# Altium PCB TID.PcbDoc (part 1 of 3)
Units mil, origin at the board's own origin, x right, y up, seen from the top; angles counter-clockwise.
Board outline 3200 x 2650 mil, 4 copper layers (Top Layer, Mid-Layer 1, Mid-Layer 2, Bottom Layer), stack 61.2 mil thick; 193 components, 108 nets, 523 pads, 202 vias.
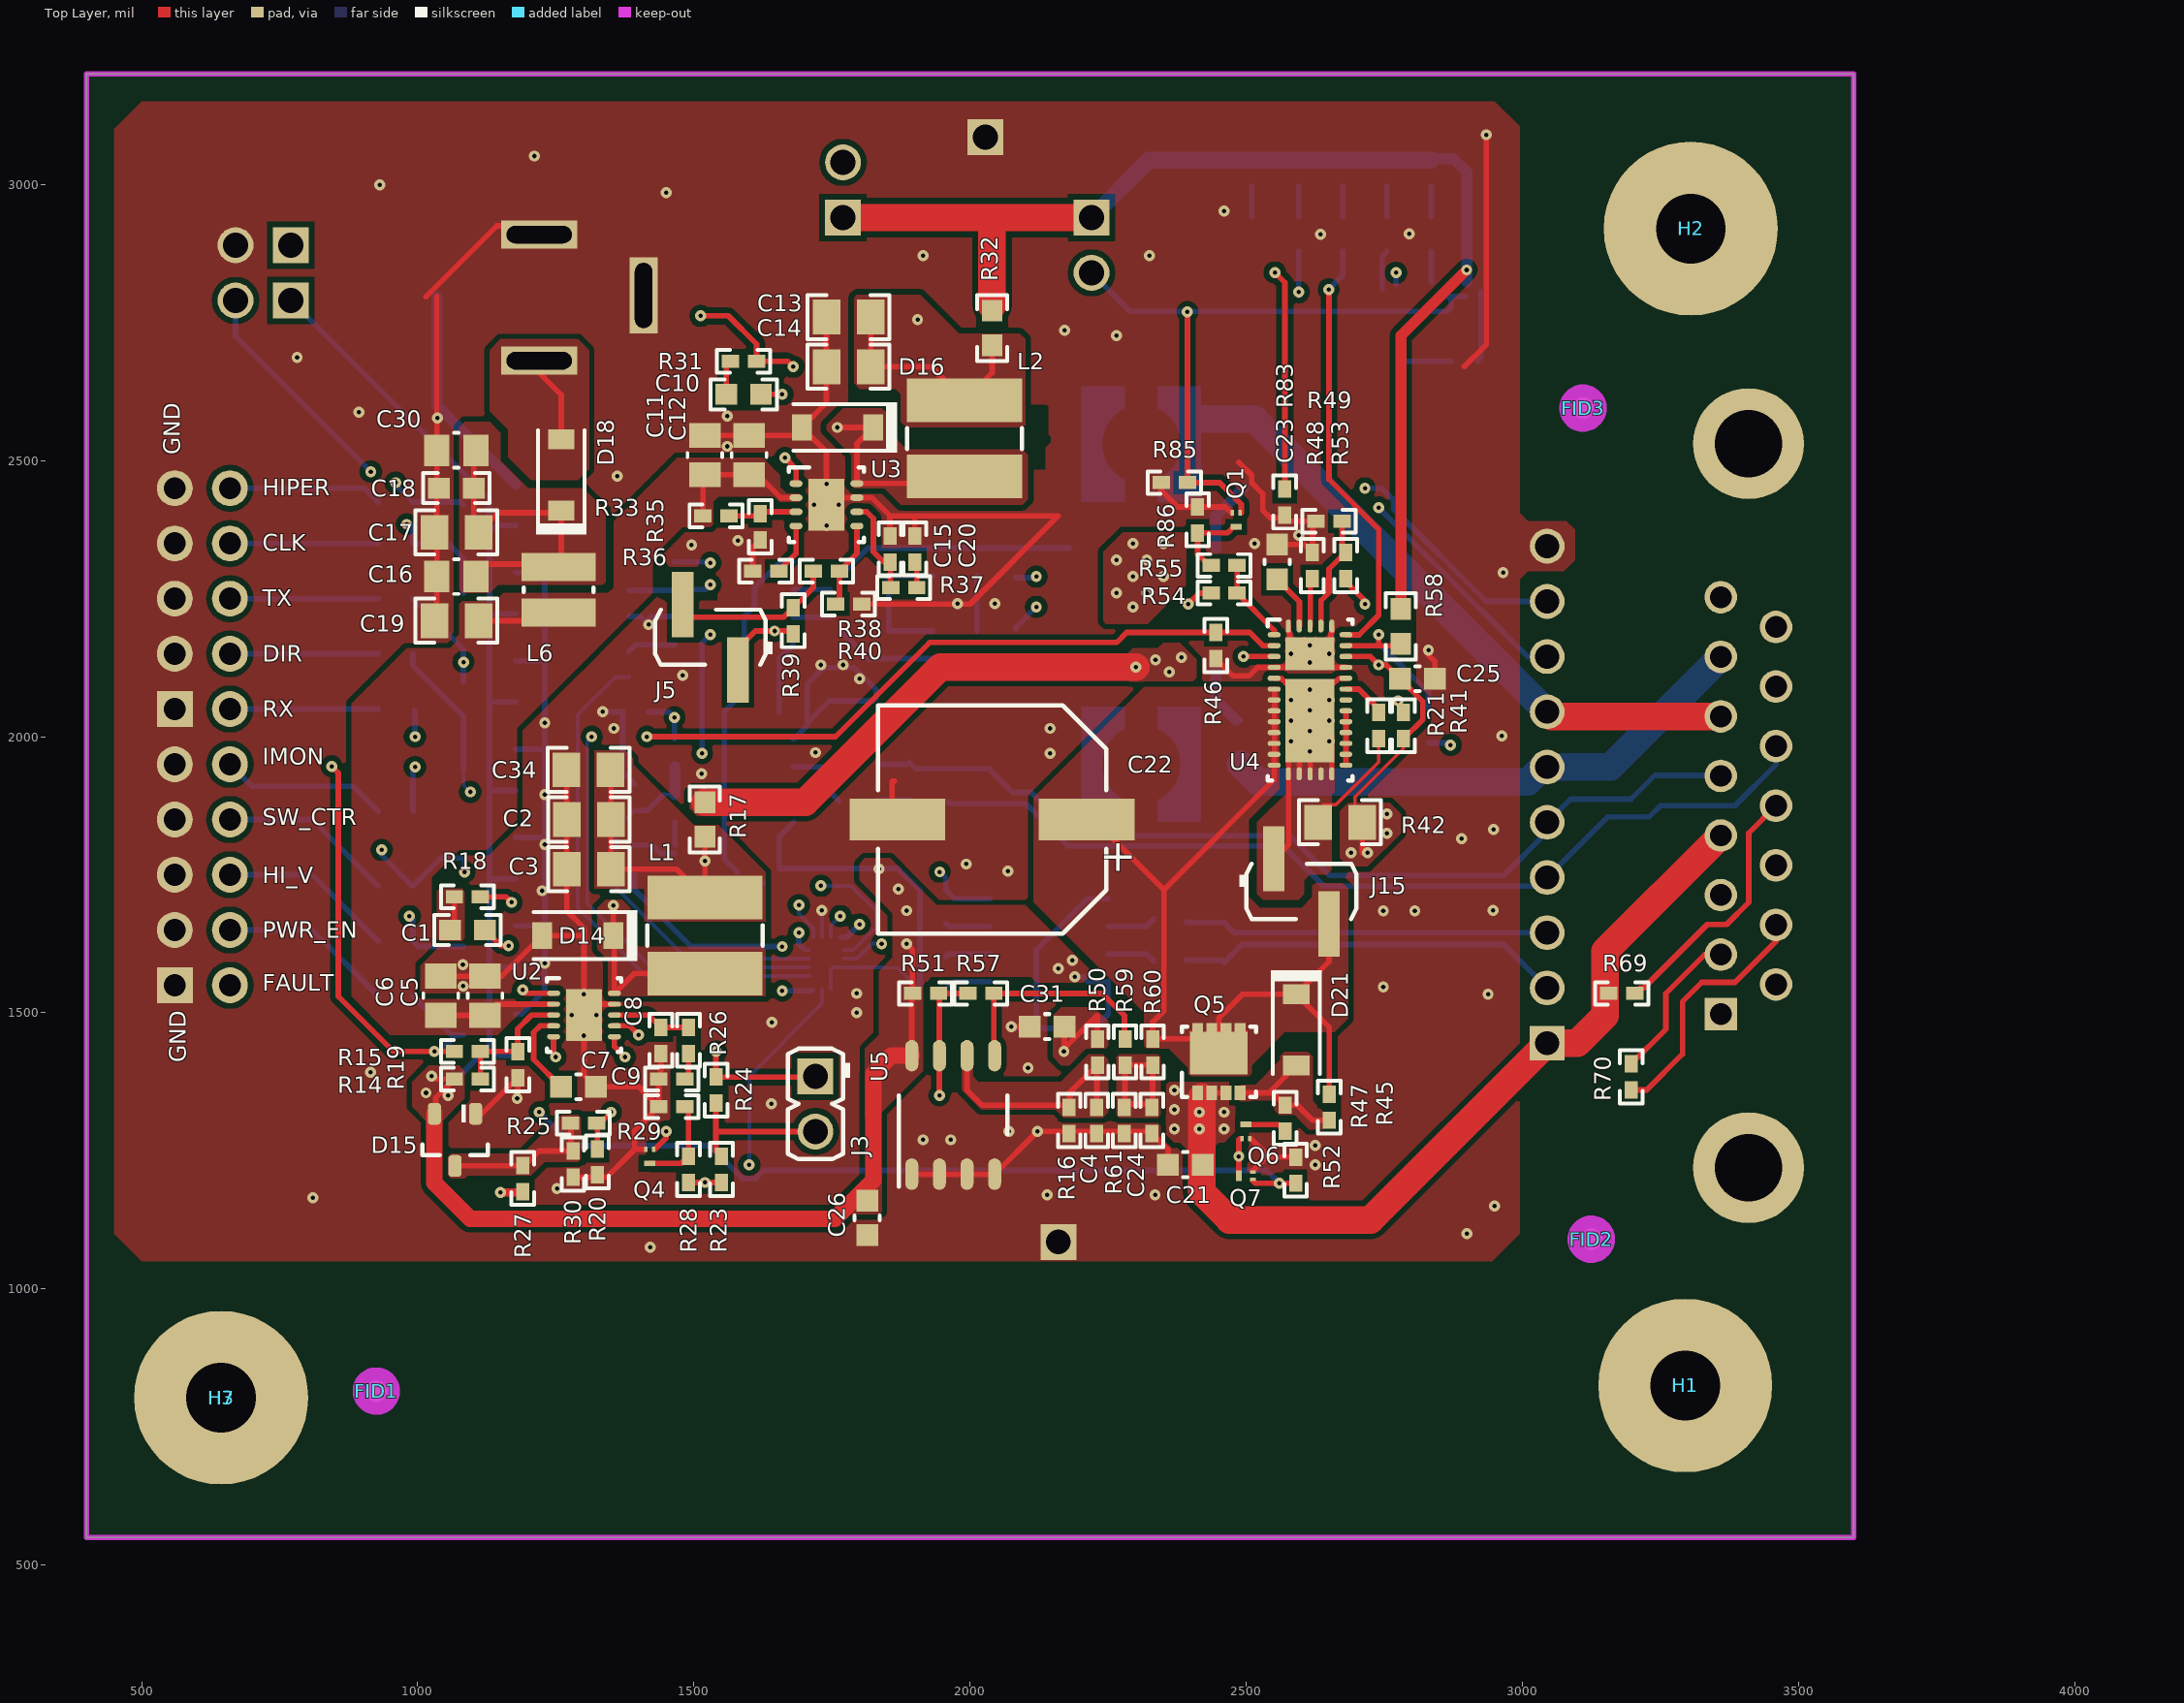
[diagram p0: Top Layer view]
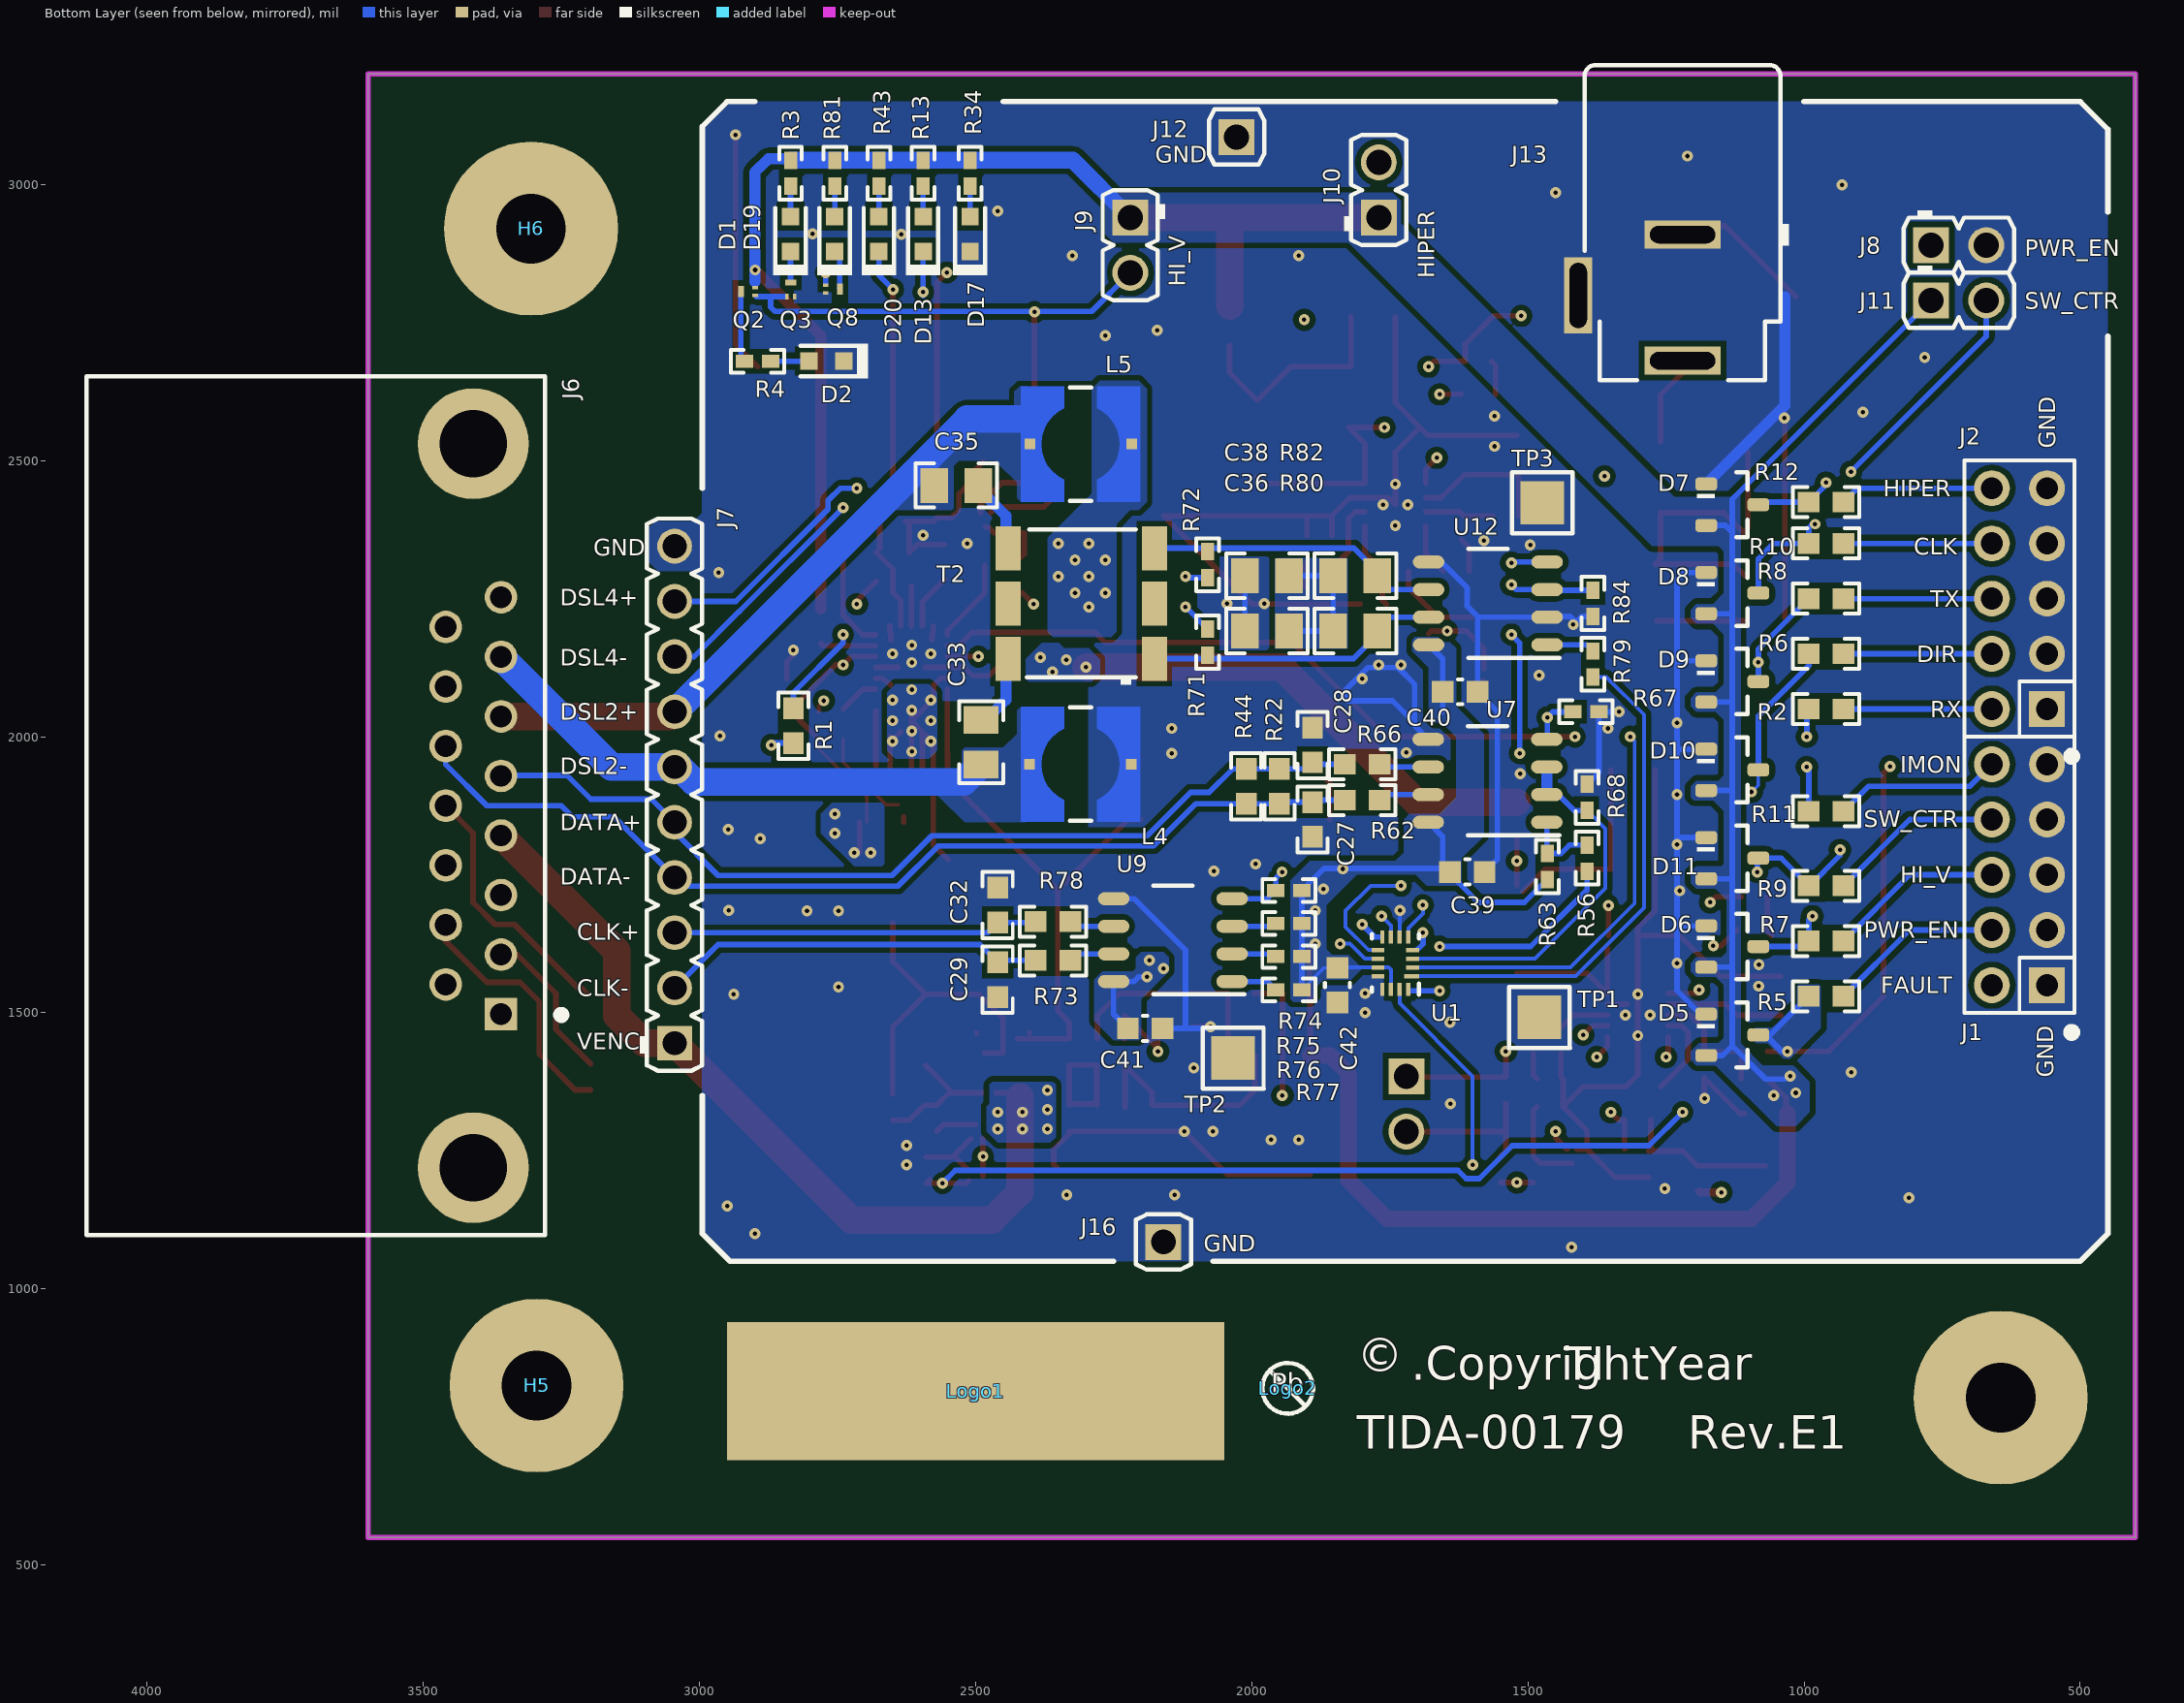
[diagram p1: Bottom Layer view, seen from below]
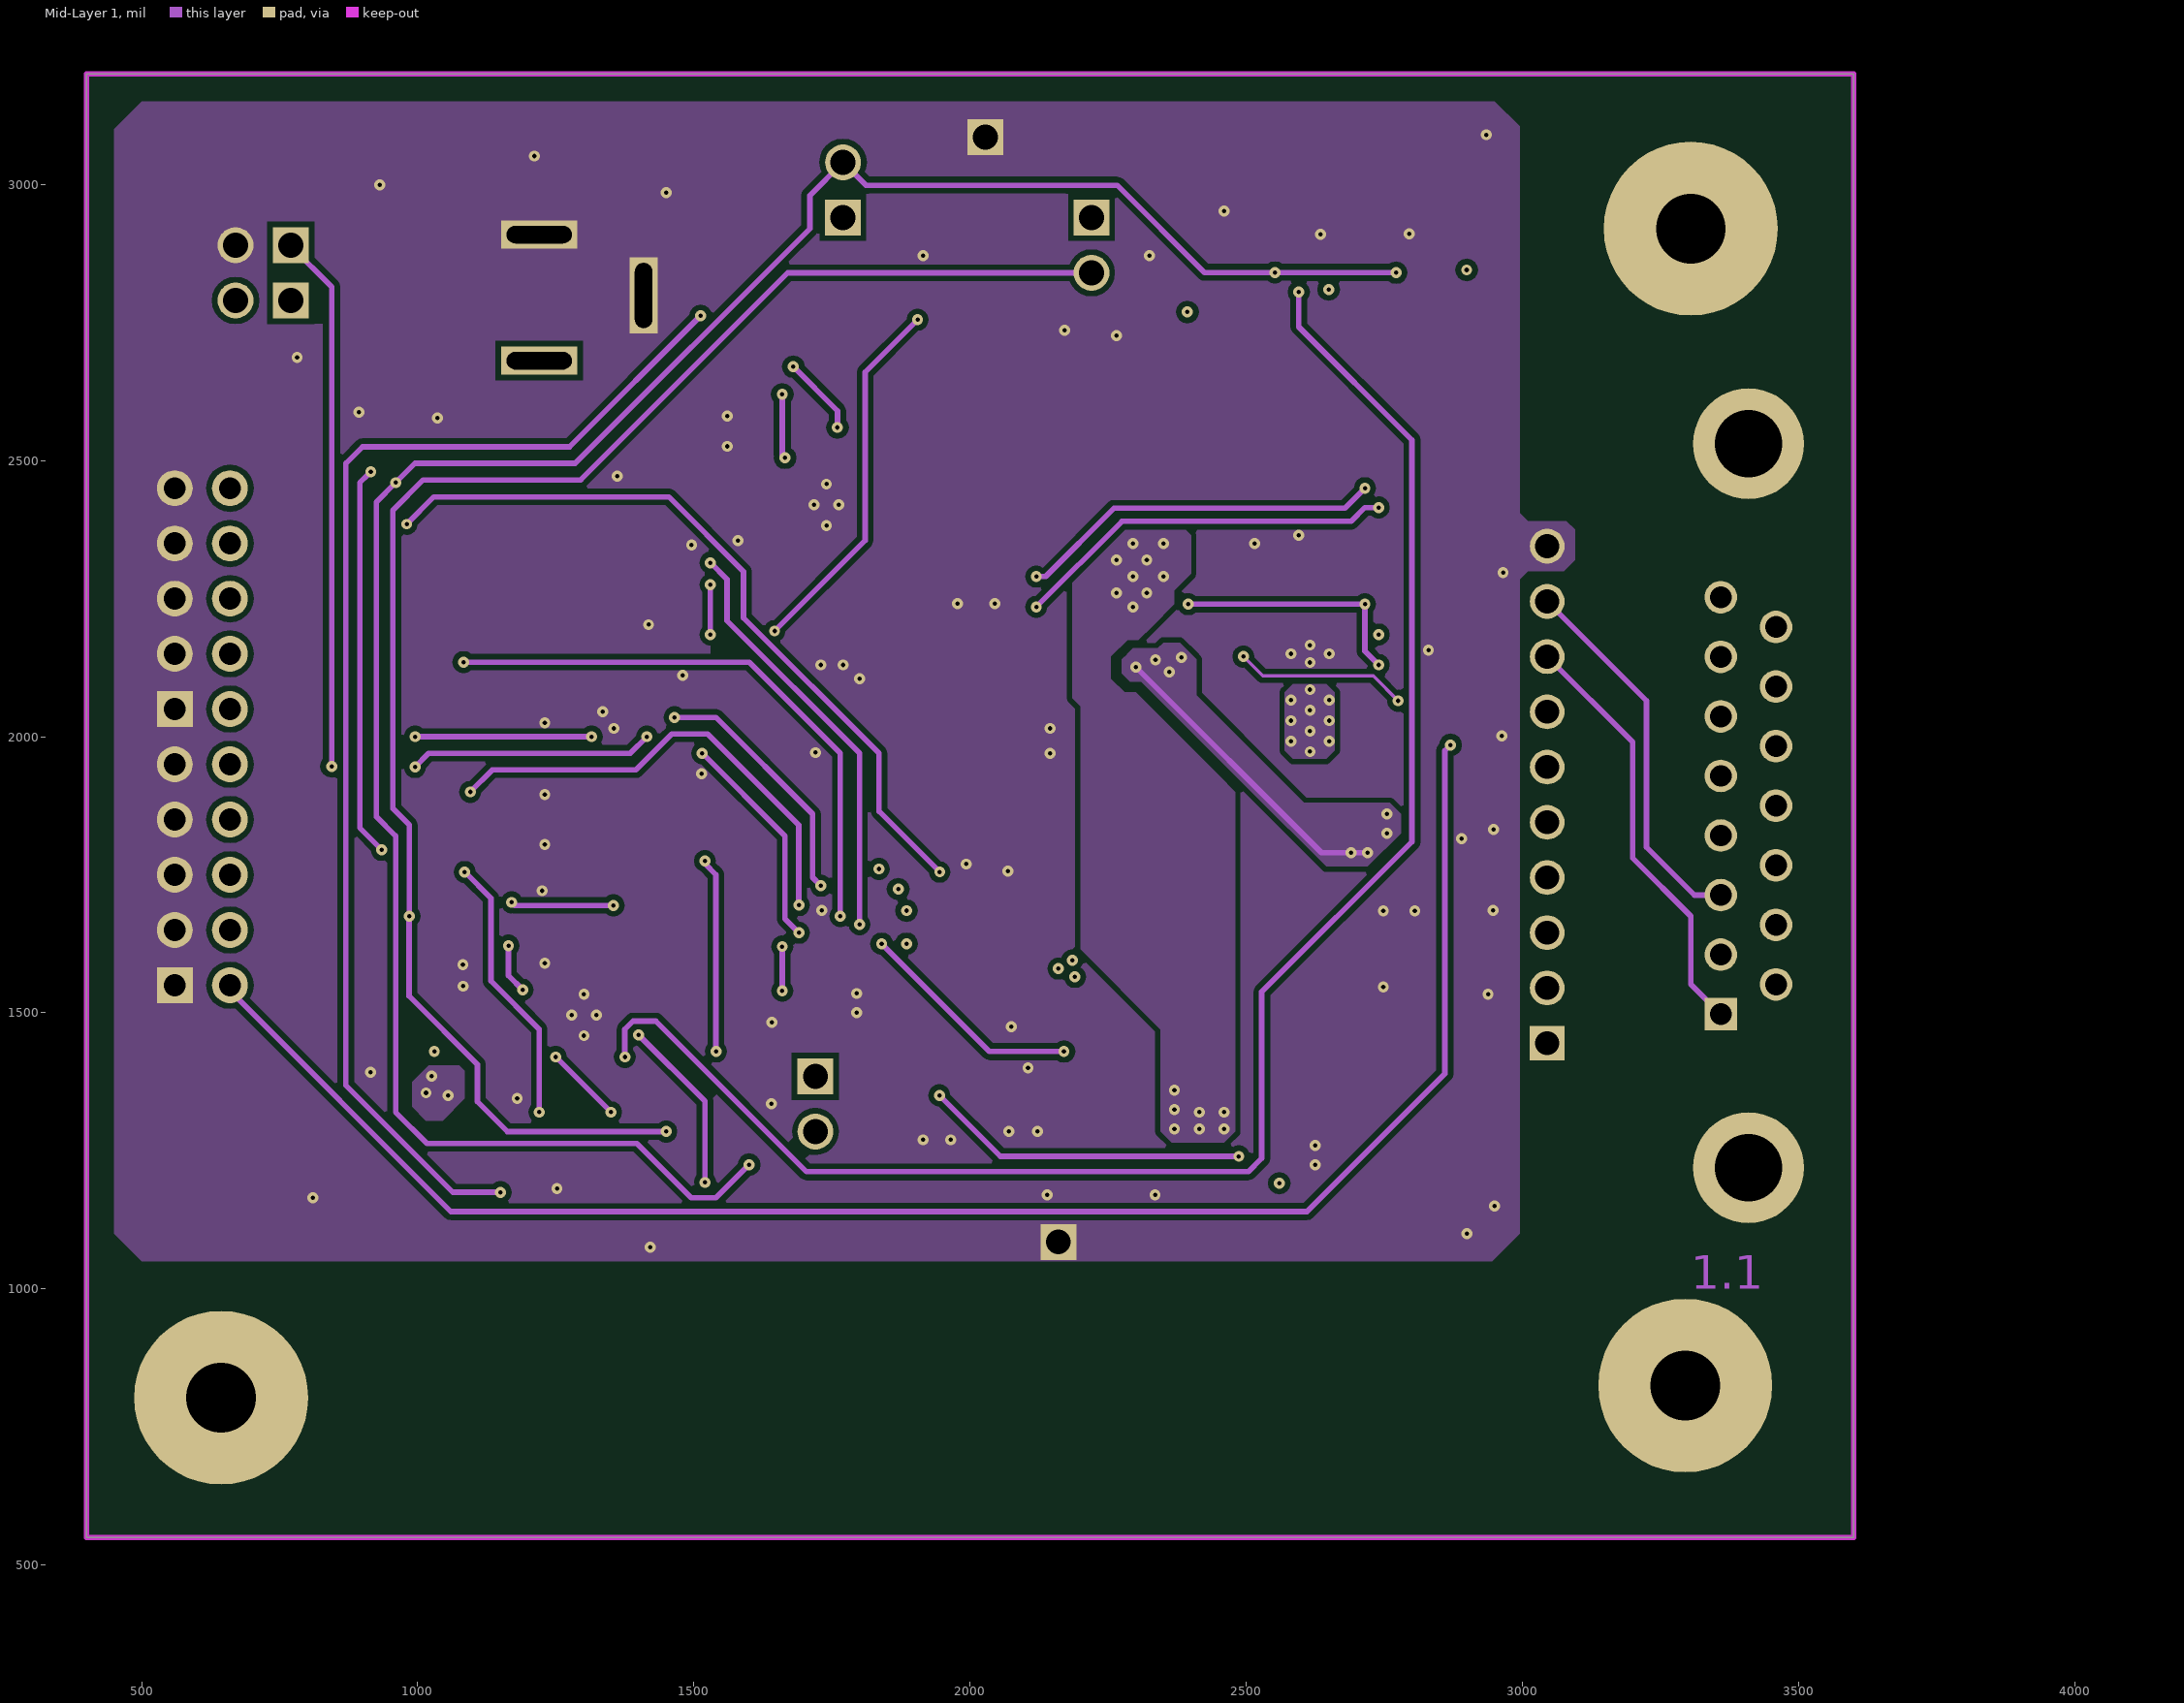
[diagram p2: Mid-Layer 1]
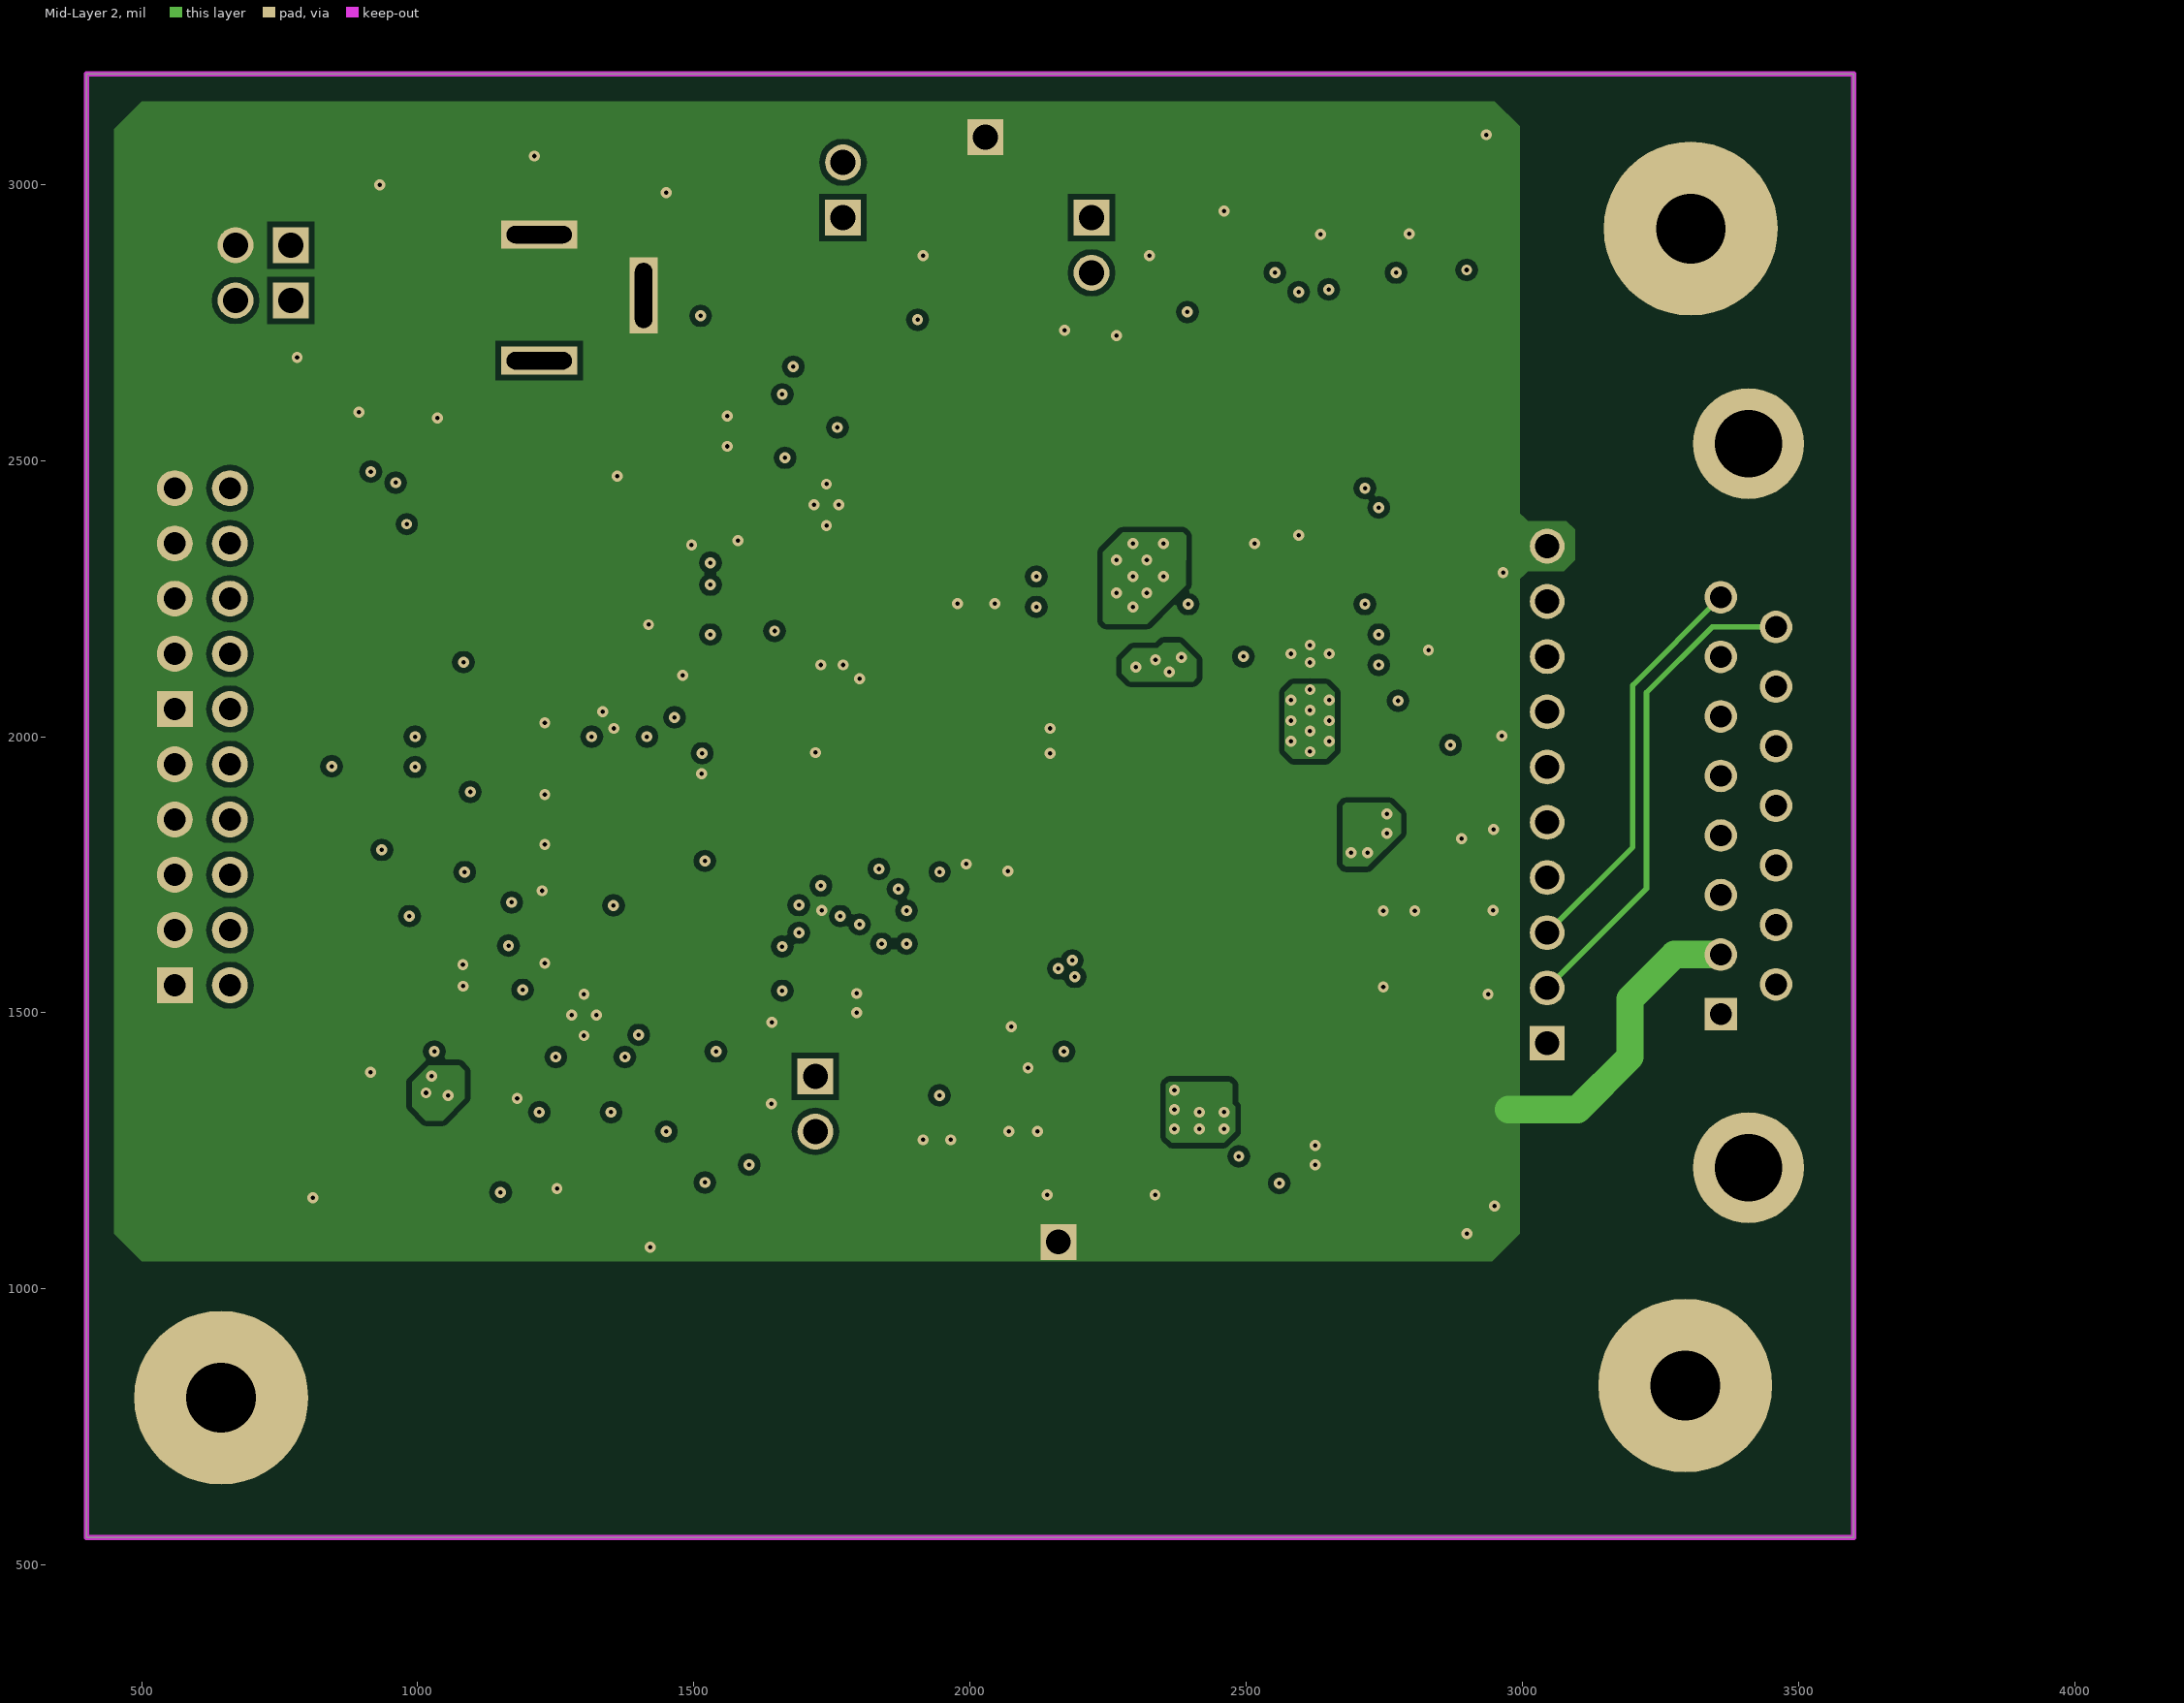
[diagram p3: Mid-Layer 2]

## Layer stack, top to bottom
Top Solder: solder mask 0.4, Solder Resist, Dk 3.5
Top Layer: signal copper 1.4
Dielectric1: core 10, FR-4, Dk 4.2
Mid-Layer 1: signal copper 1.417
Dielectric2: prepreg 35.566, FR-4, Dk 4.2
Mid-Layer 2: signal copper 1.417
Dielectric 3: core 10, FR-4, Dk 4.2
Bottom Layer: signal copper 1.4
Bottom Solder: solder mask 0.4, Solder Resist, Dk 3.5

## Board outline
400,550 3600,550 3600,3200 400,3200

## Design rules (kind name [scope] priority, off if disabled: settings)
AcuteAngle [All] p1: minimum=4.50000000000000E+0001 checktracksonly=FALSE
AssemblyTestPointUsage [All] p1: valid=2
Clearance Clearance_Q5 [(InNet('NetD21_2') AND InComponent('Q5')) vs (InNet('VENCODER') AND InComponent('Q5'))] p1: gap=5.51
Clearance Clearance_FemtoFET [IsPad AND (InComponent('Q1') or InComponent('Q2') or InComponent('Q3') or InComponent('Q4') or InComponent('Q6') or InComponent('Q7') or InComponent('Q8')) vs IsPad AND (InComponent('Q1') or InComponent('Q2') or InComponent('Q3') or InComponent('Q4') or InComponent('Q6') or InComponent('Q7') or InComponent('Q8'))] p2: gap=5.91
Clearance Clearance_Keepouts [((IsTrack Or IsArc) And Not InPoly) And IsFree and IsKeepOut vs ((IsTrack Or IsArc) And Not InPoly) And IsFree and IsKeepOut] p3: gap=0
Clearance Clearance_BoardEdge_MountingHoles [OnCopper and InComponentClass('Mounting Holes') vs IsKeepOut] p4: gap=40
Clearance Clearance_BoardEdge_Poly [OnCopper and InPoly vs IsKeepOut] p5: gap=25
Clearance Clearance_BoardEdge [OnCopper and Not InComponentClass('Logo') and not InComponentClass('FiducialMark') and not InRegion(1000,500,4000,800) and Not IsKeepout vs IsKeepOut] p6: gap=75
Clearance Clearance_Poly [InPolygon] p7: gap=10
Clearance [All] p8: gap=7.87
ComponentClearance ComponentClearance_HEADER [(ObjectKind = 'Component') And ((Name = 'J8') Or (Name='J11') or (Name='J1')or(Name='J2')) vs (ObjectKind = 'Component') And ((Name = 'J8') Or (Name='J11') or (Name='J1')or(Name='J2'))] p1: gap=0 collisioncheckmode=3 verticalgap=0 showdistances=FALSE
ComponentClearance ComponentClearance_MountingHoles_FiducialMarks [InComponentClass('Mounting Holes') vs InComponentClass('FiducialMark')] p2: gap=50 collisioncheckmode=3 verticalgap=10 showdistances=FALSE
ComponentClearance ComponentClearance_Shunt [InComponentClass('Header') vs InComponentClass('Shunt')] p3: gap=0 collisioncheckmode=3 verticalgap=0 showdistances=FALSE
ComponentClearance ComponentClearance_Logo [InComponentClass('Logo')] p4: gap=20 collisioncheckmode=3 verticalgap=10 showdistances=FALSE
ComponentClearance ComponentClearance_ScrewToNut [(HasFootprint('NY PMS 440 0025 PH')) vs (HasFootprint('Keystone_1902C'))] p5: gap=0 collisioncheckmode=3 verticalgap=0 showdistances=FALSE
ComponentClearance ComponentClearance_MountingHoles [InComponentClass('Mounting Holes')] p6: gap=50 collisioncheckmode=3 verticalgap=100000 showdistances=FALSE
ComponentClearance ComponentClearance_SmallPassives [HasFootprint('0201*') or HasFootprint('0402*') or HasFootprint('0508') or HasFootprint('0603*') or HasFootprint('0612') or HasFootprint('0805*') or HasFootprint('0815*') or HasFootprint('0830*') or HasFootprint('1206*') or HasFootprint('1210*') or HasFootprint('1808*') or HasFootprint('1812*') or HasFootprint('1825*') or HasFootprint('2010*') or HasFootprint('2220*') or HasFootprint('2225*') or HasFootprint('2512*') or HasFootprint('2728*') or HasFootprint('3518*') vs HasFootprint('0201*') or HasFootprint('0402*') or HasFootprint('0508') or HasFootprint('0603*') or HasFootprint('0612') or HasFootprint('0805*') or HasFootprint('0815*') or HasFootprint('0830*') or HasFootprint('1206*') or HasFootprint('1210*') or HasFootprint('1808*') or HasFootprint('1812*') or HasFootprint('1825*') or HasFootprint('2010*') or HasFootprint('2220*') or HasFootprint('2225*') or HasFootprint('2512*') or HasFootprint('2728*') or HasFootprint('3518*')] p7: gap=20 collisioncheckmode=3 verticalgap=10 showdistances=FALSE
ComponentClearance ComponentClearance_THtoSMT [IsThruComponent vs IsSMTComponent] p8: gap=80 collisioncheckmode=3 verticalgap=30 showdistances=FALSE
ComponentClearance ComponentClearance_THtoTH [IsThruComponent vs IsThruComponent] p9: gap=80 collisioncheckmode=3 verticalgap=30 showdistances=FALSE
ComponentClearance [All] p10: gap=40 collisioncheckmode=3 verticalgap=10 showdistances=FALSE
DiffPairsRouting [All] p1: maxlimit=100 minlimit=10 mostfreqgap=10 toplayer_minwidth=15 toplayer_maxwidth=15 toplayer_prefwidth=15 midlayer1_minwidth=15 midlayer1_maxwidth=15 midlayer1_prefwidth=15 midlayer2_minwidth=15 midlayer2_maxwidth=15 midlayer2_prefwidth=15 bottomlayer_minwidth=15 bottomlayer_maxwidth=15 bottomlayer_prefwidth=15 maxuncoupledlength=1000
FabricationTestPointUsage TestPointUsage [All] p1: valid=2 allowmultiple=FALSE
FabricationTestpoint Testpoint [All] p1: side=3 testpointundercomponent=TRUE minsize=40 maxsize=100 preferedsize=60 minholesize=0 maxholesize=40 preferedholesize=32 testpointgrid=1 allowsidetop=TRUE allowsidebottom=TRUE usegrid=TRUE gridtolerance=0.01
FanoutControl Fanout_LCC [IsLCC] p1: bgadir=Out bgaviamode=Centered fanoutstyle=Auto fanoutdirection=Alternating viagrid=1 // Fanout_LCC (Default Rule)
FanoutControl Fanout_BGA [IsBGA] p2: bgadir=Out bgaviamode=Centered fanoutstyle=Auto fanoutdirection=Alternating viagrid=1 // Fanout_BGA (Default Rule)
FanoutControl Fanout_Default [All] p4: bgadir=Out bgaviamode=Centered fanoutstyle=Auto fanoutdirection=Alternating viagrid=1 // Fanout_Default (Default Rule)
FanoutControl Fanout_Small [(CompPinCount < 5)] p5: bgadir=Out bgaviamode=Centered fanoutstyle=Auto fanoutdirection=OutThenIn viagrid=1 // Fanout_Small (Default Rule)
HoleSize [All] p1: absolutevalues=TRUE maxlimit=251 minlimit=7 maxpercent=80.000 minpercent=20.000
MinimumAnnularRing MinimumAnnularRing_ThermalPadVias [IsVia and InAnyComponent] p1: minimumring=5
MinimumAnnularRing [All] p2: minimumring=5
MinimumSolderMaskSliver MinimumSolderMaskSliver_Logo [InComponentClass('Logo') vs InComponentClass('Logo')] p1: minsoldermaskwidth=0.7
MinimumSolderMaskSliver [All] p2: minsoldermaskwidth=2
NetAntennae [not(InComponent ('U4') and IsVia)] p1: netantennaetolerance=0
PlaneConnect [All] p1: planeconnectstyle=Relief reliefexpansion=10 reliefentries=4 reliefconductorwidth=10 reliefairgap=10
PolygonConnect PolygonConnect_47 [All vs IsNamedPolygon('Top Layer -GND')] p1: connectstyle=Direct reliefconductorwidth=10 reliefentries=4 polygonreliefangle="90 Angle" airgapwidth=10
PolygonConnect PolygonConnect_46 [All vs IsNamedPolygon('Top Layer-No Net 9')] p2: connectstyle=Direct reliefconductorwidth=10 reliefentries=4 polygonreliefangle="90 Angle" airgapwidth=10
PolygonConnect PolygonConnect_45 [All vs IsNamedPolygon('Top Layer-No Net 9')] p3: connectstyle=Direct reliefconductorwidth=10 reliefentries=4 polygonreliefangle="90 Angle" airgapwidth=10
PolygonConnect PolygonConnect_44 [All vs IsNamedPolygon('Top Layer-No Net 9')] p4: connectstyle=Direct reliefconductorwidth=10 reliefentries=4 polygonreliefangle="90 Angle" airgapwidth=10
PolygonConnect PolygonConnect_43 [All vs IsNamedPolygon('Top Layer-No Net 9')] p5: connectstyle=Direct reliefconductorwidth=10 reliefentries=4 polygonreliefangle="90 Angle" airgapwidth=10
PolygonConnect PolygonConnect_42 [All vs IsNamedPolygon('Top Layer-No Net 9')] p6: connectstyle=Direct reliefconductorwidth=10 reliefentries=4 polygonreliefangle="90 Angle" airgapwidth=10
PolygonConnect PolygonConnect_41 [All vs IsNamedPolygon('Top Layer-No Net 9')] p7: connectstyle=Direct reliefconductorwidth=10 reliefentries=4 polygonreliefangle="90 Angle" airgapwidth=10
PolygonConnect PolygonConnect_40 [All vs IsNamedPolygon('Top Layer-No Net 8')] p8: connectstyle=Direct reliefconductorwidth=10 reliefentries=4 polygonreliefangle="90 Angle" airgapwidth=10
PolygonConnect PolygonConnect_39 [All vs IsNamedPolygon('Top Layer-No Net 8')] p9: connectstyle=Direct reliefconductorwidth=10 reliefentries=4 polygonreliefangle="90 Angle" airgapwidth=10
PolygonConnect PolygonConnect_38 [All vs IsNamedPolygon('Top Layer-No Net 7')] p10: connectstyle=Direct reliefconductorwidth=10 reliefentries=4 polygonreliefangle="90 Angle" airgapwidth=10
PolygonConnect PolygonConnect_37 [All vs IsNamedPolygon('Top Layer-No Net 7')] p11: connectstyle=Direct reliefconductorwidth=10 reliefentries=4 polygonreliefangle="90 Angle" airgapwidth=10
PolygonConnect PolygonConnect_36 [All vs IsNamedPolygon('Bottom Layer-No Net 3')] p12: connectstyle=Direct reliefconductorwidth=10 reliefentries=4 polygonreliefangle="90 Angle" airgapwidth=10
PolygonConnect PolygonConnect_35 [All vs IsNamedPolygon('Bottom Layer-No Net 3')] p13: connectstyle=Direct reliefconductorwidth=10 reliefentries=4 polygonreliefangle="90 Angle" airgapwidth=10
PolygonConnect PolygonConnect_34 [All vs IsNamedPolygon('Bottom Layer-No Net 3')] p14: connectstyle=Direct reliefconductorwidth=10 reliefentries=4 polygonreliefangle="90 Angle" airgapwidth=10
PolygonConnect PolygonConnect_33 [All vs IsNamedPolygon('Bottom Layer-No Net 2')] p15: connectstyle=Direct reliefconductorwidth=10 reliefentries=4 polygonreliefangle="90 Angle" airgapwidth=10
PolygonConnect PolygonConnect_32 [All vs IsNamedPolygon('Bottom Layer-No Net')] p16: connectstyle=Direct reliefconductorwidth=10 reliefentries=4 polygonreliefangle="90 Angle" airgapwidth=10
PolygonConnect PolygonConnect_31 [All vs IsNamedPolygon('Bottom Layer-No Net 1')] p17: connectstyle=Direct reliefconductorwidth=10 reliefentries=4 polygonreliefangle="90 Angle" airgapwidth=10
PolygonConnect PolygonConnect_30 [All vs IsNamedPolygon('Bottom Layer-No Net')] p18: connectstyle=Direct reliefconductorwidth=10 reliefentries=4 polygonreliefangle="90 Angle" airgapwidth=10
PolygonConnect PolygonConnect_29 [All vs IsNamedPolygon('Bottom Layer-No Net 1')] p19: connectstyle=Direct reliefconductorwidth=10 reliefentries=4 polygonreliefangle="90 Angle" airgapwidth=10
PolygonConnect PolygonConnect_28 [All vs IsNamedPolygon('Top Layer -GND')] p20: connectstyle=Direct reliefconductorwidth=10 reliefentries=4 polygonreliefangle="90 Angle" airgapwidth=10
PolygonConnect PolygonConnect_27 [All vs IsNamedPolygon('Top Layer -GND')] p21: connectstyle=Direct reliefconductorwidth=10 reliefentries=4 polygonreliefangle="90 Angle" airgapwidth=10
PolygonConnect PolygonConnect_26 [All vs IsNamedPolygon('Top Layer -GND')] p22: connectstyle=Direct reliefconductorwidth=10 reliefentries=4 polygonreliefangle="90 Angle" airgapwidth=10
PolygonConnect PolygonConnect_25 [All vs IsNamedPolygon('Top Layer -VIN')] p23: connectstyle=Direct reliefconductorwidth=10 reliefentries=4 polygonreliefangle="90 Angle" airgapwidth=10
PolygonConnect PolygonConnect_24 [All vs IsNamedPolygon('Top Layer -VIN')] p24: connectstyle=Direct reliefconductorwidth=10 reliefentries=4 polygonreliefangle="90 Angle" airgapwidth=10
PolygonConnect PolygonConnect_23 [All vs IsNamedPolygon('Top Layer -VIN')] p25: connectstyle=Direct reliefconductorwidth=10 reliefentries=4 polygonreliefangle="90 Angle" airgapwidth=10
PolygonConnect PolygonConnect_22 [All vs IsNamedPolygon('Top Layer-No Net 4')] p26: connectstyle=Direct reliefconductorwidth=10 reliefentries=4 polygonreliefangle="90 Angle" airgapwidth=10
PolygonConnect PolygonConnect_21 [All vs IsNamedPolygon('Top Layer-No Net 6')] p27: connectstyle=Direct reliefconductorwidth=10 reliefentries=4 polygonreliefangle="90 Angle" airgapwidth=10
PolygonConnect PolygonConnect_20 [All vs IsNamedPolygon('Top Layer-No Net')] p28: connectstyle=Direct reliefconductorwidth=10 reliefentries=4 polygonreliefangle="90 Angle" airgapwidth=10
PolygonConnect PolygonConnect_19 [All vs IsNamedPolygon('Top Layer-No Net 1')] p29: connectstyle=Direct reliefconductorwidth=10 reliefentries=4 polygonreliefangle="90 Angle" airgapwidth=10
PolygonConnect PolygonConnect_18 [All vs IsNamedPolygon('Top Layer -PHASE')] p30: connectstyle=Direct reliefconductorwidth=10 reliefentries=4 polygonreliefangle="90 Angle" airgapwidth=10
PolygonConnect PolygonConnect_17 [All vs IsNamedPolygon('Bottom Layer -GND')] p31: connectstyle=Direct reliefconductorwidth=10 reliefentries=4 polygonreliefangle="90 Angle" airgapwidth=10
PolygonConnect PolygonConnect_16 [All vs IsNamedPolygon('Top Layer-No Net 3')] p32: connectstyle=Direct reliefconductorwidth=10 reliefentries=4 polygonreliefangle="90 Angle" airgapwidth=10
PolygonConnect PolygonConnect_15 [All vs IsNamedPolygon('Mid-Layer 2 -GND')] p33: connectstyle=Direct reliefconductorwidth=10 reliefentries=4 polygonreliefangle="90 Angle" airgapwidth=10
PolygonConnect PolygonConnect_14 [All vs IsNamedPolygon('Top Layer -VENCODER')] p34: connectstyle=Direct reliefconductorwidth=10 reliefentries=4 polygonreliefangle="90 Angle" airgapwidth=10
PolygonConnect PolygonConnect_13 [All vs IsNamedPolygon('Top Layer-No Net 2')] p35: connectstyle=Direct reliefconductorwidth=10 reliefentries=4 polygonreliefangle="90 Angle" airgapwidth=10
PolygonConnect PolygonConnect_12 [All vs IsNamedPolygon('Top Layer-No Net 5')] p36: connectstyle=Direct reliefconductorwidth=10 reliefentries=4 polygonreliefangle="90 Angle" airgapwidth=10
PolygonConnect PolygonConnect_11 [All vs IsNamedPolygon('Top Layer -VOUT_EFUSE')] p37: connectstyle=Direct reliefconductorwidth=10 reliefentries=4 polygonreliefangle="90 Angle" airgapwidth=10
PolygonConnect PolygonConnect_10 [All vs IsNamedPolygon('Top Layer-No Net 3')] p38: connectstyle=Direct reliefconductorwidth=10 reliefentries=4 polygonreliefangle="90 Angle" airgapwidth=10
PolygonConnect PolygonConnect_9 [All vs IsNamedPolygon('Top Layer-No Net')] p39: connectstyle=Direct reliefconductorwidth=10 reliefentries=4 polygonreliefangle="90 Angle" airgapwidth=10
PolygonConnect PolygonConnect_8 [All vs IsNamedPolygon('Mid-Layer 2 -GND')] p40: connectstyle=Direct reliefconductorwidth=10 reliefentries=4 polygonreliefangle="90 Angle" airgapwidth=10
PolygonConnect PolygonConnect_7 [All vs IsNamedPolygon('Top Layer -VENCODER')] p41: connectstyle=Direct reliefconductorwidth=10 reliefentries=4 polygonreliefangle="90 Angle" airgapwidth=10
PolygonConnect PolygonConnect_6 [All vs IsNamedPolygon('Top Layer -PHASE')] p42: connectstyle=Direct reliefconductorwidth=10 reliefentries=4 polygonreliefangle="90 Angle" airgapwidth=10
PolygonConnect PolygonConnect_5 [All vs IsNamedPolygon('Top Layer -VOUT_EFUSE')] p43: connectstyle=Direct reliefconductorwidth=10 reliefentries=4 polygonreliefangle="90 Angle" airgapwidth=10
PolygonConnect PolygonConnect_4 [All vs IsNamedPolygon('Bottom Layer -GND')] p44: connectstyle=Direct reliefconductorwidth=10 reliefentries=4 polygonreliefangle="90 Angle" airgapwidth=10
PolygonConnect PolygonConnect_3 [All vs IsNamedPolygon('Mid-Layer 2-No Net')] p45: connectstyle=Direct reliefconductorwidth=10 reliefentries=4 polygonreliefangle="90 Angle" airgapwidth=10
PolygonConnect PolygonConnect_2 [All vs IsNamedPolygon('GND')] p46: connectstyle=Direct reliefconductorwidth=10 reliefentries=4 polygonreliefangle="90 Angle" airgapwidth=10
PolygonConnect PolygonConnect_1 [All vs IsNamedPolygon('Bottom Layer-No Net')] p47: connectstyle=Direct reliefconductorwidth=10 reliefentries=4 polygonreliefangle="90 Angle" airgapwidth=10
PolygonConnect [All] p48: connectstyle=Relief reliefconductorwidth=10 reliefentries=4 polygonreliefangle="90 Angle" airgapwidth=10
RoutingVias ThermalPadVias [IsVia and InAnyComponent] p1: holewidth=7.87 width=19.68 viastyle="Through Hole" minholewidth=7 minwidth=19.68 maxholewidth=13 maxwidth=23.62
RoutingVias [All] p2: holewidth=16 width=34 viastyle="Through Hole" minholewidth=7.87 minwidth=19 maxholewidth=40 maxwidth=65
SilkToBoardRegionClearance [Not ((IsComment or IsDesignator) And (Hide <> 'False')) and not (InRegion(1000,500,4000,800) or InRegion(1600,4700,2200,4785) or InRegion(4700,2500,4850,4250))] p1:
SilkToSilkClearance SilkToSilkClearance_Pb-FreeLogo [(HasFootprint('Pb-Free_Overlay_Medium') OR HasFootprint('Pb-Free_Overlay_Small')) vs (HasFootprint('Pb-Free_Overlay_Medium') OR HasFootprint('Pb-Free_Overlay_Small'))] p1: silktosilkclearance=0
SilkToSilkClearance [All] p2: silktosilkclearance=0
SilkToSolderMaskClearance "Silk to Solder Mask Opening" [not (IsVia) vs not (IsVia)] p1: minsilkscreentomaskgap=0 clearancetoexposedcopper=FALSE
SolderMaskExpansion [All] p1: expansion=1.97
UnpouredPolygon [All] p1: allowunpoured=FALSE
Width [All] p1: maxlimit=100 minlimit=6 preferedwidth=10 checkconnectedcopper=TRUE
13 further rules are at their usual default settings.

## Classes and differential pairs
component class "Mounting Holes": H1 H2 H3
component class Logo: Logo1
component class TID_Hardware: FID1 FID2 FID3 H1 H2 H3 H5 H6 H7 Logo1 Logo2
component class FiducialMark: FID1 FID2 FID3
component class Header: J1 J2 J3 J5 J7 J8 J9 J10 J11 J12 J15 J16
component class MUX: C42 D1 D2 D5 D6 D7 D8 D9 D10 D11 D19 J1 J2 J8 J9 J10 J11 Q2 Q3 Q8 R1 R2 R3 R4 R5 R6 R7 R8 R9 R10 R11 R12 R52 R58 R81 R83 R85 U1
component class Power: C1 C2 C3 C5 C6 C7 C8 C9 C10 C11 C12 C13 C14 C15 C16 C17 C18 C19 C20 C30 C34 D13 D14 D15 D16 D17 D18 GND3 J3 J5 J8 J13 L1 L2 L6 Q4 R13 R14 R15 R17 R18 R19 R20 R23 R24 R25 R26 R27 R28 R29 R30 R31 R32 R33 R34 R35 R36 R37 R38 R39 R40 U2 U3
component class Protections: C4 C21 C22 C23 C24 C25 C26 C31 D20 D21 J8 J12 J15 J16 Q1 Q5 Q6 Q7 R16 R21 R41 R42 R43 R45 R46 R47 R48 R49 R50 R51 R53 R54 R55 R57 R59 R60 R61 R86 U4 U5
component class RS485: C27 C28 C29 C32 C33 C35 C36 C38 C39 C40 C41 J6 J7 J8 L4 L5 L7 R22 R44 R56 R62 R63 R66 R67 R68 R69 R70 R71 R72 R73 R74 R75 R76 R77 R78 R79 R80 R82 R84 T2 TP1 TP2 TP3 U7 U9 U12

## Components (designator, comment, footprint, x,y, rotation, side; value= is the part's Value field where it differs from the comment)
C1 "GRM188R72A104KA35D" 0603 1090,1650 r0 top
C2 "C2012X5R1E106K125AB" 0805_HV 1309.8,1850 r180 top
C3 "C2012X5R1E106K125AB" 0805_HV 1310,1760 r180 top
C4 "885012205044" 0402 2229.5,1305 r270 top
C5 "C2012X7S2A105K125AB" 0805_145 1121.8,1530.86 r90 top
C6 "C2012X7S2A105K125AB" 0805_145 1041.8,1530.86 r90 top
C7 "885012206036" 0603_095 1291.05,1366.02 r0 top
C8 "885012005056" 0402 1440,1450 r270 top
C9 "885012205031" 0402 1460,1380 r180 top
C10 "GRM188R72A104KA35D" 0603 1590,2620 r0 top
C11 "C2012X7S2A105K125AB" 0805_145 1520,2510 r90 top
C12 "C2012X7S2A105K125AB" 0805_145 1600,2510 r90 top
C13 "C2012X5R1E106K125AB" 0805_HV 1780,2760 r180 top
C14 "C2012X5R1E106K125AB" 0805_HV 1780,2670 r180 top
C15 "885012005043" 0402 1855,2340 r90 top
C16 "C2012X7S2A105K125AB" 0805_145 1070,2290 r180 top
C17 "C0805C104K1RACTU" 0805_HV 1070,2370 r180 top
C18 "C1608X7R2A223K" 0603 1070,2450 r180 top
C19 "C0805C104K1RACTU" 0805_HV 1070,2210 r180 top
C20 "GRM155R71E472KA01D" 0402 1900,2340 r90 top
C21 "885012206071" 0603_095 2390,1225 r180 top
C22 "865080457015" WCAP_ASLI_1000x1050 2040,1850 r180 top
C23 "885012206048" 0603_095 2556.06,2316.36 r90 top
C24 "885012205044" 0402 2329.5,1305 r270 top
C25 "885012206046" 0603_095 2810,2105 r180 top
C26 "885012206046" 0603_095 1813.78,1128.63 r90 top
C27 "885012006060" 0603 1890,1850 r90 bottom
C28 "885012006060" 0603 1890,1985 r90 bottom
C29 "885012006060" 0603 2460,1560 r90 bottom
C30 "C2012X7S2A105K125AB" 0805_145 1070,2518.7 r180 top
C31 "885012206046" 0603_095 2139.5,1475 r0 top
C32 "885012006060" 0603 2460,1695 r90 bottom
C33 "885012207102" 0805_HV 2490,1990 r90 bottom
C34 "C2012X5R1E106K125AB" 0805_HV 1309.29,1940 r180 top
C35 "885012207102" 0805_HV 2535,2455 r180 bottom
C36 "GRM21BR71E225KA73L" 0805_HV 1972.5,2191.39 r0 bottom
C38 "GRM2195C1H103JA01D" 0805_HV 1972.5,2291.39 r0 bottom
C39 "885012206046" 0603_095 1610,1755 r0 bottom
C40 "885012206046" 0603_095 1622.82,2081.39 r0 bottom
C41 "885012206046" 0603_095 2192.82,1471.71 r0 bottom
C42 "885012206046" 0603_095 1845,1550 r90 bottom
D1 "150060GS75000" WL-SMCW_GREEN 2835.09,2910.29 r90 bottom
D2 "150060YS75000" WL-SMCW_YELLOW 2770,2680 r0 bottom
D5 "BAT54SLT1G" SOT-23 1130,1460 r180 bottom
D6 "BAT54SLT1G" SOT-23 1130,1620 r180 bottom
D7 "BAT54SLT1G" SOT-23 1130,2420 r180 bottom
D8 "BAT54SLT1G" SOT-23 1130,2260 r180 bottom
D9 "BAT54SLT1G" SOT-23 1130,2100 r180 bottom
D10 "BAT54SLT1G" SOT-23 1130,1940 r180 bottom
D11 "BAT54SLT1G" SOT-23 1130,1780 r180 bottom
D13 "150060RS75000" WL-SMCW_RED 2595.09,2910.29 r90 bottom
D14 "MBR0580-TP" SOD-123 1290,1640 r180 top
D15 "MMBZ5225BLT1G" SOT-23 1067.44,1269.83 r270 top
D16 "MBR0580-TP" SOD-123 1760,2560 r180 top
D17 "150060GS75000" WL-SMCW_GREEN 2510.05,2910.29 r90 bottom
D18 "MBR0580-TP" SOD-123 1259.89,2474.35 r90 top
D19 "150060BS75000" WL-SMCW_Blue 2755.09,2910.29 r90 bottom
D20 "150060GS75000" WL-SMCW_GREEN 2675.09,2910.29 r90 bottom
D21 "MMSZ4694-V" SOD-123 2590.6,1469.04 r270 top
FID1 "Fiducial" Fiducial10-20 925,815 r0 top
FID2 "Fiducial" Fiducial10-20 3125,1090 r0 top
FID3 "Fiducial" Fiducial10-20 3110,2595 r0 top
H1 "NY PMS 440 0025 PH" "NY PMS 440 0025 PH" 3295,825 r0 top locked
H2 "NY PMS 440 0025 PH" "NY PMS 440 0025 PH" 3305,2920 r0 top locked
H3 "NY PMS 440 0025 PH" "NY PMS 440 0025 PH" 644,803 r180 top locked
H5 "1902C" Keystone_1902C#1 3295,825 r180 bottom locked
H6 "1902C" Keystone_1902C#1 3305,2920 r180 bottom locked
H7 "1902C" Keystone_1902C#2 644.23,802.99 r180 top locked
J1 "PEC05DAAN" CONN_PEC05DAAN 610,1750 r90 bottom
J2 "PEC05DAAN" CONN_PEC05DAAN 610,2250 r90 bottom
J3 "61300211121" WURTH_61300211121 1720,1335 r270 top
J5 "61000218321" Wurth_61000218321 1530,2180 r180 top
J6 "09 66 252 6610" "Harting_09 66 252 6610" 3870,1875 r0 bottom
J7 "61301011121" Wurth_61301011121 3045,1895 r90 bottom
J8 "61300211121" WURTH_61300211121 720,2890 r180 bottom
J9 "61300211121" WURTH_61300211121 2220,2890 r270 bottom
J10 "61300211121" WURTH_61300211121 1770,2990 r90 bottom
J11 "61300211121" WURTH_61300211121 720,2790 r180 bottom
J12 "61300111121" WURTH_61300111121 2027.62,3085.87 r180 bottom
J13 "694106301002" Wurth_694106301002 1220,2795 r180 bottom
J15 "61000218321" Wurth_61000218321 2600,1720 r0 top
J16 "61300111121" WURTH_61300111121 2160,1085 r90 bottom
L1 "74408943101" WE-SPC_4838 1520,1640 r90 top
L2 "74408943101" WE-SPC_4838 1990,2540 r90 top
L4 "744043101" WE-TPC_4828 2310,1950 r180 bottom
L5 "744043101" WE-TPC_4828 2310,2530 r0 bottom
L6 "74438334068" WE-MAPI_3012 1254.91,2266.19 r270 top
Logo1 "Texas Instruments" TI_Stacked_SolderMask_Small 2500,815 r180 bottom
Logo2 "Pb-Free Symbol" Pb-Free_Overlay_Small 1935,820 r180 bottom
Q1 "CSD17483F4T" YJC0003A 2482.13,2392.6 r180 top
Q2 "CSD23381F4" YJC0003A 2912.18,2806.25 r90 bottom
Q3 "CSD17483F4T" YJC0003A 2834.9,2809.82 r180 bottom
Q4 "CSD17483F4T" YJC0003A 1420,1240 r180 top
Q5 "CSD25402Q3A" TRANS_NexFET_Q3A 2450.6,1419.04 r90 top
Q6 "CSD17483F4T" YJC0003A 2499.5,1285 r0 top
Q7 "CSD17483F4T" YJC0003A 2499.5,1205 r90 top
Q8 "CSD17483F4T" YJC0003A 2758.65,2810.35 r270 bottom
R1 "CRCW060310R0JNEAHP" 0603 2830,2020 r90 bottom
R2 "CRCW060310R0JNEAHP" 0603 960,2050 r0 bottom
R3 "CRCW0402560RJNED" 0402 2835.09,3020.29 r90 bottom
R4 "CRCW0402560RJNED" 0402 2895,2680 r0 bottom
R5 "CRCW060310R0JNEAHP" 0603 960,1530 r0 bottom
R6 "CRCW060310R0JNEAHP" 0603 960,2150 r0 bottom
R7 "CRCW060310R0JNEAHP" 0603 960,1630 r0 bottom
R8 "CRCW060310R0JNEAHP" 0603 960,2250 r0 bottom
R9 "CRCW060310R0JNEAHP" 0603 960,1730 r0 bottom
R10 "CRCW060310R0JNEAHP" 0603 960,2350 r0 bottom
R11 "CRCW060310R0JNEAHP" 0603 960,1865 r0 bottom
R12 "CRCW060310R0JNEAHP" 0603 960,2425 r0 bottom
R13 "CRCW0402560RJNED" 0402 2595.09,3020.29 r90 bottom
R14 "CRCW0402100KJNED" 0402 1090,1380 r180 top
R15 "CRCW040251R0JNED" 0402 1090,1430 r180 top
R16 "CRCW04024K99FKED" 0402 2179.5,1305 r90 top
R17 "CRCW06030000Z0EA" 0603 1520,1850 r90 top
R18 "CRCW04020000Z0ED" 0402 1090,1710 r0 top
R19 "CRCW0402100KJNED" 0402 1181.05,1406.02 r90 top
R20 "CRCW0402150KJNED" 0402 1325,1230 r90 top
R21 "CRCW04020000Z0ED" 0402 2740,2020 r270 top
R22 "CRCW0603240RJNEA" 0603 1950,1910 r270 bottom
R23 "CRCW040249K9FKED" 0402 1550,1216.22 r270 top
R24 "CRCW040251R0JNED" 0402 1540,1360 r90 top
R25 "CRCW0402100RJNED" 0402 1300,1300 r0 top
R26 "CRCW040249K9FKED" 0402 1490,1450 r90 top
R27 "CRCW04029K10JNED" 0402 1190,1200 r90 top
R28 "CRCW04023K92FKED" 0402 1490,1216.38 r90 top
R29 "CRCW04025K11FKED" 0402 1460,1330 r180 top
R30 "CRCW04021K30JNED" 0402 1281.05,1226.02 r90 top
R31 "CRCW04020000Z0ED" 0402 1590,2680 r0 top
R32 "CRCW06030000Z0EA" 0603 2040,2740 r90 top
R33 "CRCW0402100KJNED" 0402 1540,2400 r0 top
R34 "CRCW0402560RJNED" 0402 2510.05,3020.29 r90 bottom
R35 "CRCW040212K0JNED" 0402 1620,2380 r90 top
R36 "CRCW0402150KJNED" 0402 1630,2300 r0 top
R37 "CRCW040226K1FKED" 0402 1880,2270 r180 top
R38 "CRCW040231K6FKED" 0402 1740,2300 r180 top
R39 "CRCW040251R0JNED" 0402 1680,2210 r270 top
R40 "CRCW040210K0FKED" 0402 1780,2240 r180 top
R41 "CRCW040251R1FKED" 0402 2785,2020 r270 top
R42 "ERJ-6RSFR10V" 0805_HV 2670,1845 r0 top
R43 "CRCW0402560RJNED" 0402 2675.09,3020.29 r90 bottom
R44 "CRCW0603240RJNEA" 0603 2010,1910 r270 bottom
R45 "CRCW04021K20JNED" 0402 2650.6,1329.04 r90 top
R46 "CRCW04021K15FKED" 0402 2445,2165 r90 top
R47 "CRCW0402510RJNED" 0402 2570.6,1309.04 r90 top
R48 "CRCW04024K99FKED" 0402 2620,2310 r270 top
R49 "CRCW040210K0JNED" 0402 2650,2390 r0 top
R50 "CRCW04026K34FKED" 0402 2230.6,1429.04 r90 top
R51 "CRCW04024K70JNED" 0402 1919.5,1535 r180 top
R52 "CRCW040210K0JNED" 0402 2589.5,1215 r270 top
R53 "CRCW040220K0JNED" 0402 2680,2310 r90 top
R54 "CRCW040249K9FKED" 0402 2460,2260 r0 top
R55 "CRCW04026K34FKED" 0402 2460,2310 r0 top
R56 "CRCW040222R0JNED" 0402 1392.82,1780.09 r90 bottom
R57 "CRCW0402309KFKED" 0402 2019.5,1535 r180 top
R58 "CRCW060310K0JNEA" 0603 2780,2200 r90 top
R59 "CRCW040249K9FKED" 0402 2280.6,1429.04 r90 top
R60 "CRCW040223K7FKED" 0402 2330.6,1429.04 r90 top
R61 "CRCW04024K99FKED" 0402 2279.5,1305 r90 top
R62 "CRCW060310R0JNEAHP" 0603 1800,1885 r0 bottom
R63 "CRCW040210K0JNED" 0402 1465,1765 r270 bottom
R66 "CRCW060310R0JNEAHP" 0603 1800,1950 r0 bottom
R67 "CRCW040210K0JNED" 0402 1395,2045 r0 bottom
R68 "CRCW040210K0JNED" 0402 1392.82,1890.09 r270 bottom
R69 "CRCW04020000Z0ED" 0402 3180,1535 r0 top
R70 "CRCW04020000Z0ED" 0402 3197.27,1383.86 r270 top
R71 "CRCW04020000Z0ED" 0402 2080,2171.32 r90 bottom
R72 "CRCW04020000Z0ED" 0402 2080,2311.38 r270 bottom
R73 "CRCW060310R0JNEAHP" 0603 2360,1595 r0 bottom
R74 "CRCW040210K0JNED" 0402 1932.82,1721.71 r180 bottom
R75 "CRCW040210K0JNED" 0402 1932.82,1661.71 r180 bottom
R76 "CRCW040210K0JNED" 0402 1932.82,1601.71 r180 bottom
R77 "CRCW040210K0JNED" 0402 1932.82,1541.71 r180 bottom
R78 "CRCW060310R0JNEAHP" 0603 2360,1665 r0 bottom
R79 "CRCW040222R0JNED" 0402 1382.5,2131.39 r90 bottom
R80 "CRCW080556R2FKEA" 0805_HV 1812.5,2191.39 r180 bottom
R81 "CRCW0402560RJNED" 0402 2755.09,3020.29 r90 bottom
R82 "CRCW080556R2FKEA" 0805_HV 1812.5,2291.39 r0 bottom
R83 "CRCW040210K0JNED" 0402 2570,2425 r90 top
R84 "CRCW040210K0JNED" 0402 1382.5,2241.39 r90 bottom
R85 "CRCW040210K0JNED" 0402 2370,2460 r0 top
R86 "CRCW04028K06FKED" 0402 2412.13,2392.6 r270 top
T2 "PE-68386NL" PULSE_PE-68386NL 2308.71,2241.2 r0 bottom
TP1 "TESTPOINT" OXLEY_SMOX_060_B1_LP 1479.07,1491.7 r180 bottom
TP2 "TESTPOINT" OXLEY_SMOX_060_B1_LP 2033.64,1418 r180 bottom
TP3 "TESTPOINT" OXLEY_SMOX_060_B1_LP 1474.15,2423.58 r180 bottom
U1 "SN74CBTLV3257RSVR" RSV0016A 1740,1590 r0 bottom
U2 "TPS54060DRCT" DRC0010J 1301.05,1496.02 r0 top
U3 "TPS54061DRBR" DRB0008B 1740,2420 r0 top
U4 "TPS24750RUV" RUV0036A 2615.71,2066.46 r0 top
U5 "LM2903D" D0008A_N 1969.5,1315 r90 top
U7 "SN65HVD78D" D0008A_N 1573.13,1920.09 r0 bottom
U9 "SN65HVD78D" D0008A_N 2142.82,1631.71 r0 bottom
U12 "SN65HVD78D" D0008A_N 1572.5,2241.39 r0 bottom

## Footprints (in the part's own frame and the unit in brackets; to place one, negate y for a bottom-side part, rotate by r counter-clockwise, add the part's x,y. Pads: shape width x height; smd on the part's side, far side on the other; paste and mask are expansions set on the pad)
0402 [mm] "0402 from SM-752 data"
  rect 0.8x0.6 smd: 1(-0.6,0) 2(0.6,0)
  silkscreen extent -1.22,-0.52 1.22,0.52, body extent -0.55,-0.3 0.55,0.3, height 0.6
0603 [mm] "0603 from SM-752 data"
  rect 1x0.95 smd: 1(-0.8,0) 2(0.8,0)
  silkscreen extent -1.52,-0.69 1.52,0.69, body extent -0.87,-0.47 0.87,0.47, height 0.85
0603_095 [mm] "0603_095"
  rect 1x1 smd: 1(-0.8,0) 2(0.8,0)
  silkscreen extent -0.1,-0.58 0.1,0.58, body extent -0.87,-0.48 0.87,0.48, height 0.95
0805_145 [mm] "0805 / 1.45mm height"
  rect 1.15x1.45 smd: 1(-0.9,0) 2(0.9,0)
  silkscreen extent -0.1,-0.8 0.1,0.8, body extent -1.1,-0.72 1.1,0.72, height 1.45
0805_HV [mil] "0805 with 30mil clearance between pads"
  rect 50x63 smd: 1(-40,0) 2(40,0)
  silkscreen extent -74,-40 74,40, body extent -43,-29 43,29, height 43
CONN_PEC05DAAN [mm] "SULLINS"
  rect 1.65x1.65 hole 1.016 mask+0: 1(-5.08,-1.27)
  round 1.65 hole 1.016 mask+0: 2(-5.08,1.27) 3(-2.54,-1.27) 4(-2.54,1.27) 5(0,-1.27) 6(0,1.27) 7(2.54,-1.27) 8(2.54,1.27) 9(5.08,-1.27) 10(5.08,1.27)
  silkscreen extent -7.45,-2.6 6.35,2.54, body extent -6.35,-2.54 6.35,2.54, height 8.38
D0008A_N [mm] "SOIC, 8-Leads, Body 4.9x3.9mm, Pitch 1.27mm, IPC Medium Density"
  oval 1.45x0.6 smd: 1(-2.725,1.905) 2(-2.725,0.635) 3(-2.725,-0.635) 4(-2.725,-1.905) 5(2.725,-1.905) 6(2.725,-0.635) 7(2.725,0.635) 8(2.725,1.905)
  silkscreen extent -3.3,-2.5 0.9,2.5, body extent -3,-2.45 3,2.45, height 1.63
DRB0008B [mm] "SON, 8-Leads, Body 3x3mm, Pitch 0.65mm, Thermal Pad 2.4x1.65mm, TI Recommended"
  oval 0.6x0.3 smd: 1(-1.4,0.975) 2(-1.4,0.325) 3(-1.4,-0.325) 4(-1.4,-0.975) 5(1.4,-0.975) 6(1.4,-0.325) 7(1.4,0.325) 8(1.4,0.975)
  rect 1.65x2.4 smd paste-1.2: 9(0,0)
  silkscreen extent -1.73,-1.73 1.73,1.73, body extent -1.57,-1.57 1.58,1.58, height 1.01
DRC0010J [mm] "SON, 10-Leads, Body 3x3mm, Pitch 0.5mm, Thermal Pad 2.4x1.65mm, TI Recommended"
  rrect100% 0.6x0.24 smd: 1(-1.4,1) 2(-1.4,0.5) 3(-1.4,0) 4(-1.4,-0.5) 5(-1.4,-1) 6(1.4,-1) 7(1.4,-0.5) 8(1.4,0) 9(1.4,0.5) 10(1.4,1)
  rrect6% 1.65x2.4 smd paste-0.825: 11(0,0)
  silkscreen extent -1.7,-1.7 1.7,1.7, body extent -1.55,-1.55 1.55,1.55, height 1.01
Fiducial10-20 [mm]
  round 1 smd mask+0.5: 1(0,0)
  Top Layer keep-out circle w1.178: c0,0 r0.5
"Harting_09 66 252 6610" [mm] "Harting"
  rect 1.5x1.5 hole 1 paste+0: 1(-12.97,9.59)
  round 1.5 hole 1 paste+0: 2(-12.97,6.85) 3(-12.97,4.11) 4(-12.97,1.37) 5(-12.97,-1.37) 6(-12.97,-4.11) 7(-12.97,-6.85) 8(-12.97,-9.59) 9(-10.43,8.22) 10(-10.43,5.48) 11(-10.43,2.74) 12(-10.43,0) 13(-10.43,-2.74) 14(-10.43,-5.48) 15(-10.43,-8.22)
  round 5.1 hole 3.1 paste+0: 16(-11.7,-16.65) 17(-11.7,16.65)
  silkscreen extent -15.86,-19.75 6.1,19.75, body extent -15,-19.75 6.1,19.75, height 13.6
Keystone_1902C#1 [mil] "Hex Standoff, 4-40 threaded, nylon"
  body extent -145,-126 146,126, height 501
Keystone_1902C#2 [mil] "Hex Standoff, 4-40 threaded, nylon"
  round 1 on Mech3: 0(0,0)
  body extent -145,-126 146,126, height 501
"NY PMS 440 0025 PH" [mm] "4-40 nylon screw and mounting hole"
  round 8 hole 3.2: 1(0,0)
  body extent -3.3,-3.3 3.3,3.3, height 2.69
OXLEY_SMOX_060_B1_LP [mm] "Test-Point, SMD"
  rect 2x2 smd mask+0.048: 1(0,0)
  silkscreen extent -1.4,-1.4 1.4,1.4, body extent -0.99,-1 1,1, height 1.4
Pb-Free_Overlay_Small [mil]
  silkscreen extent -46,-46 46,46
PULSE_PE-68386NL [mil] "PULSE"
  rect 45x80 smd: 1(-132.5,100) 2(-132.5,0) 3(-132.5,-100) 4(132.5,-100) 5(132.5,0) 6(132.5,100)
  silkscreen extent -98,-134 98,148, body extent -177,-133 177,133, height 99
RSV0016A [mm] "QFN, 16-Leads, Body 1.8x2.6mm, Pitch 0.4mm, TI Recommended"
  rect 0.7x0.2 smd: 1(-0.75,0.6)
  rect 0.6x0.2 smd: 2(-0.8,0.2) 3(-0.8,-0.2) 4(-0.8,-0.6) 9(0.8,-0.6) 10(0.8,-0.2) 11(0.8,0.2) 12(0.8,0.6)
  rect 0.2x0.6 smd: 5(-0.6,-1.2) 6(-0.2,-1.2) 7(0.2,-1.2) 8(0.6,-1.2) 13(0.6,1.2) 14(0.2,1.2) 15(-0.2,1.2) 16(-0.6,1.2)
  silkscreen extent -1.08,-1.33 1.08,1.45, body extent -0.92,-1.32 0.92,1.33, height 0.56
RUV0036A [mm]
  oval 0.6x0.24 smd: 1(-1.65,3) 2(-1.65,2.5) 3(-1.65,2) 4(-1.65,1.5) 5(-1.65,1) 6(-1.65,0.5) 7(-1.65,0) 8(-1.65,-0.5) 9(-1.65,-1) 10(-1.65,-1.5) 11(-1.65,-2) 12(-1.65,-2.5) 13(-1.65,-3) 19(1.65,-3) 20(1.65,-2.5) 21(1.65,-2) 22(1.65,-1.5) 23(1.65,-1) 24(1.65,-0.5) 25(1.65,0) 26(1.65,0.5) 27(1.65,1) 28(1.65,1.5) 29(1.65,2) 30(1.65,2.5) 31(1.65,3)
  oval 0.24x0.6 smd: 14(-1,-3.4) 15(-0.5,-3.4) 16(0,-3.4) 17(0.5,-3.4) 18(1,-3.4) 32(1,3.4) 33(0.5,3.4) 34(0,3.4) 35(-0.5,3.4) 36(-1,3.4)
  rect 2.25x1.514 smd paste-1: 37(0,2.118)
  rect 2.25x3.836 smd paste-1.2: 38(0,-0.957)
  silkscreen extent -1.95,-3.7 1.95,3.7, body extent -1.82,-3.57 1.82,3.57, height 1.02
SOD-123 [mm] "On Semi recommended land pattern"
  rect 0.915x1.22 smd: 1(-1.637,0) 2(1.637,0)
  silkscreen extent -2.74,-1.17 2.03,1.17, body extent -1.93,-0.9 1.93,0.9, height 1.35
SOT-23 [mm] "SOT23, 3-Leads, Body 2.9x1.3mm, Pitch 0.95mm, Lead Span 2.5mm, IPC Medium Density"
  rrect50% 1x0.6 smd: 1(-1.2,0.95) 2(-1.2,-0.95) 3(1.2,0)
  silkscreen extent -1.63,-1.5 0.7,1.5, body extent -1.16,-1.45 1.21,1.45, height 1
TI_Stacked_SolderMask_Small [mil]
  rect 900x250 smd paste-125 mask-125: 0(0,0)
TRANS_NexFET_Q3A [mm] "TI"
  rect 0.68x0.5 smd paste-1 mask+0.076: 1(-1.625,0.975) 2(-1.625,0.325) 3(-1.625,-0.325) 4(-1.625,-0.975)
  rect 0.41x0.5 smd paste-1 mask+0.076: 5(1.385,-0.975) 6(1.385,-0.325) 7(1.385,0.325) 8(1.385,0.975)
  rect 1.96x2.65 smd paste-3 mask+0.076: 9(0.205,0)
  Top Layer region: 1,1.1 1.24,1.1 1.24,1.325 1,1.325
  Top Layer region: 1,-1.325 1.24,-1.325 1.24,-1.1 1,-1.1
  silkscreen extent -1.82,-1.7 1.42,1.7, body extent -1.85,-1.65 1.45,1.66, height 0.91
WCAP_ASLI_1000x1050 [mm] "SMD, 2-Leads, Dia 10mm"
  rect 4.4x1.9 smd: 1(-4.35,0) 2(4.35,0)
  silkscreen extent -5.25,-5.25 5.25,5.25, body extent -5.26,-5.26 5.26,5.26, height 10.51
WE-MAPI_3012 [mm] "SMD, 2-Leads, Body 3.2x3.2mm"
  rect 1.3x3.4 smd: 1(-1.05,0) 2(1.05,0)
  silkscreen extent -0.1,-1.6 0.1,1.6, body extent -1.5,-1.5 1.5,1.5, height 1.2
WE-SPC_4838 [mm] "WURTH"
  rect 2x5.3 smd: 1(-1.75,0) 2(1.75,0)
  silkscreen extent -0.48,-2.65 0.48,2.65, body extent -2.55,-2.55 2.55,2.55, height 4.1
WE-TPC_4828 [mm] "Wurth Elektronik recommended land pattern"
  rect 0.5x0.5 smd: 1(-2.35,0) 2(2.325,0)
  Top Layer region: -0.75,1.64 -1.005,1.504 -1.279,1.279 -1.504,1.005 -1.671,0.692 -1.774,0.353 -1.809,0 -1.774,-0.353 -1.671,-0.692 -1.504,-1.005 -1.279,-1.279 -1.005,-1.504 -0.75,-1.64 -0.75,-2.65 -2.75,-2.65 -2.75,2.65 -0.75,2.65
  Top Layer region: 0.75,1.64 1.005,1.504 1.279,1.279 1.504,1.005 1.671,0.692 1.774,0.353 1.809,0 1.774,-0.353 1.671,-0.692 1.504,-1.005 1.279,-1.279 1.005,-1.504 0.75,-1.64 0.75,-2.65 2.75,-2.65 2.75,2.65 0.75,2.65
  silkscreen extent -0.5,-2.6 0.5,2.63, body extent -2.51,-2.51 2.51,2.51, height 2
WL-SMCW_Blue [mm] "SMD, 2-Leads, Body 1.6x0.8mm"
  rect 0.8x0.8 smd: 1(-0.8,0) 2(0.8,0)
  silkscreen extent -1.9,-0.8 1.2,0.8, body extent -0.85,-0.45 0.85,0.45, height 0.8
WL-SMCW_GREEN [mm] "WURTH"
  rect 0.8x0.8 smd: 1(-0.8,0) 2(0.8,0)
  silkscreen extent -1.9,-0.8 1.2,0.8, body extent -0.85,-0.45 0.85,0.45, height 0.8
WL-SMCW_RED [mm] "WURTH"
  rect 0.8x0.8 smd: 1(-0.8,0) 2(0.8,0)
  silkscreen extent -1.9,-0.8 1.2,0.8, body extent -0.85,-0.45 0.85,0.45, height 0.8
WL-SMCW_YELLOW [mm] "WURTH"
  rect 0.8x0.8 smd: 1(-0.8,0) 2(0.8,0)
  silkscreen extent -1.9,-0.8 1.2,0.8, body extent -0.85,-0.45 0.85,0.45, height 0.8
Wurth_61000218321 [mm] "Header, 2.54mm, 2x1, SMT"
  rect 1x3 smd: 1(-1.27,1.5) 2(1.27,-1.5)
  silkscreen extent -2.86,-1.27 2.54,1.27, body extent -2.54,-2.5 2.54,2.5, height 6.3
WURTH_61300111121 [mm] "Header, 2.54 mm, 1x1, TH"
  rect 1.65x1.65 hole 1.15: 1(0,0)
  silkscreen extent -1.27,-1.27 1.27,1.27, body extent -1.27,-1.27 1.27,1.27, height 8.54
WURTH_61300211121 [mm] "Header, 2.54mm, 2x1, TH"
  rect 1.65x1.65 hole 1.15: 1(-1.27,0)
  round 1.65 hole 1.15: 2(1.27,0)
  silkscreen extent -2.54,-1.27 2.54,1.6, body extent -2.54,-1.27 2.54,1.27, height 8.54
Wurth_61301011121 [mm] "Header, 2.54mm, 10x1, TH"
  rect 1.6x1.6 hole 1.1: 1(-11.43,0)
  round 1.6 hole 1.1: 2(-8.89,0) 3(-6.35,0) 4(-3.81,0) 5(-1.27,0) 6(1.27,0) 7(3.81,0) 8(6.35,0) 9(8.89,0) 10(11.43,0)
  silkscreen extent -12.7,-1.27 12.7,1.6, body extent -12.7,-1.27 12.7,1.27, height 8.54
Wurth_694106301002 [mm] "WR-DC DC Power Jack, R/A, TH"
  rect 3.5x1.3 hole 0.8 slot 3 at 0 deg: 1(0,-2.9) 2(0,2.9)
  rect 1.3x3.5 hole 0.8 slot 3 at 90 deg: 3(-4.8,0.1)
  silkscreen extent -4.5,-3.8 4.9,10.7, body extent -4.9,-3.8 4.5,10.7, height 10.63
YJC0003A [mm] "TI"
  rect 0.16x0.26 smd: 1(-0.175,-0.325) 2(0.175,-0.325)
  rect 0.51x0.26 smd: 3(0,0.325)
  body extent -0.32,-0.52 0.32,0.52, height 0.35

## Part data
C1 C10: "CAP, CERM, 0.1 µF, 100 V, +/- 10%, X7R, 0603"
C2 C3 C13 C14 C34: "CAP, CERM, 10uF, 25V, +/-10%, X5R, 0805"
C4 C24: "CAP, CERM, 1000 pF, 25 V, +/- 10%, X7R, 0402"
C5 C6 C11 C12 C16 C30: "CAP, CERM, 1 µF, 100 V, +/- 10%, X7S, 0805"
C7: "CAP, CERM, 2200 pF, 16 V, +/- 10%, X7R, 0603_095"
C8: "CAP, CERM, 15 pF, 50 V, +/- 5%, C0G/NP0, 0402"
C9: "CAP, CERM, 0.01 µF, 16 V, +/- 10%, X7R, 0402"
C15: "CAP, CERM, 33 pF, 25 V, +/- 5%, C0G/NP0, 0402"
C17 C19: "CAP, CERM, 0.1 µF, 100 V, +/- 10%, X7R, 0805"
C18: "CAP, CERM, 0.022 µF, 100 V, +/- 10%, X7R, 0603"
C20: "CAP, CERM, 4700 pF, 25 V, +/- 10%, X7R, 0402"
C21: "CAP, CERM, 0.1 µF, 25 V, +/- 10%, X7R, 0603_095"
C22: "CAP, AL, 470 µF, 25 V, +/- 20%, 0.15 ohm, SMD"
C23: "CAP, CERM, 0.22 µF, 16 V, +/- 10%, X7R, 0603_095"
C25 C26 C31 C39 C40 C41 C42: "CAP, CERM, 0.1 µF, 16 V, +/- 10%, X7R, 0603_095"
C27 C28 C29 C32: "CAP, CERM, 330 pF, 50 V, +/- 5%, C0G/NP0, 0603"
C33 C35: "CAP, CERM, 0.47 µF, 50 V, +/- 10%, X7R, 0805"
C36: "CAP, CERM, 2.2 µF, 25 V, +/- 10%, X7R, 0805"
C38: "CAP, CERM, 0.01 µF, 50 V, +/- 5%, C0G/NP0, 0805"
D1 D17 D20: "LED, Green, SMD"
D2: "LED, Yellow, SMD"
D5 D6 D7 D8 D9 D10 D11: "Diode, Schottky, 30 V, 0.2 A, SOT-23"
D13: "LED, Red, SMD"
D14 D16 D18: "Diode, Schottky, 80 V, 0.5 A, SOD-123"
D15: "Diode, Zener, 3 V, 225 mW, SOT-23"
D19: "LED, Blue, SMD"
D21: "Diode, Zener, 8.2 V, 500 mW, SOD-123"
FID1 FID2 FID3: "Fiducial mark.  There is nothing to buy or mount."
H1 H2 H3: "Machine Screw, Round, #4-40 x 1/4, Nylon, Philips panhead"
H5 H6 H7: "Standoff, Hex, 0.5\"L #4-40 Nylon"
J1 J2: "Header, 100mil, 5x2, Tin, TH"
J3 J8 J9 J10 J11: "Header, 2.54 mm, 2x1, Gold, TH"
J5 J15: "Header, 2.54mm, 2x1, Gold, SMT"
J6: "D-Sub-15, 17Pos, TH"
J7: "Header, 2.54mm, 10x1, Gold, TH"
J12 J16: "Header, 2.54 mm, 1x1, Gold, TH"
J13: "WR-DC DC Power Jack, R/A, TH"
L1 L2: "Inductor, Shielded Drum Core, Ferrite, 100 µH, 0.52 A, 0.77 ohm, SMD"
L4 L5: "Inductor, Shielded Drum Core, Ferrite, 100 µH, 0.3 A, 0.52 ohm, SMD"
L6: "Inductor, Shielded, 6.8 µH, 0.88 A, 0.3682 ohm, SMD"
Logo1: library part TI_Logo, "Texas Instrument Corporate Signature"
Logo2: library part Pb-Free
Q1 Q3 Q4 Q6 Q7 Q8: "MOSFET, N/P-CH, 30 V, 1.5 A,"
Q2: "MOSFET, P-CH, -12 V, -2.3 A,"
Q5: "MOSFET, P-CH, -20 V, -15 A, SON 3.3x3.3mm"
R1 R2 R5 R6 R7 R8 R9 R10 R11 R12 R62 R66 R73 R78: "RES, 10 ohm, 5%, 0.25W, 0603"
R3 R4 R13 R34 R43 R81: "RES, 560, 5%, 0.063 W, 0402"
R14 R19 R33: "RES, 100 k, 5%, 0.063 W, 0402"
R15 R24 R39: "RES, 51, 5%, 0.063 W, 0402"
R16 R48 R61: "RES, 4.99 k, 1%, 0.063 W, 0402"
R17 R32: "RES, 0 ohm, 5%, 0.1W, 0603"
R18 R21 R31 R69 R70 R71 R72: "RES, 0, 5%, 0.063 W, 0402"
R20 R36: "RES, 150 k, 5%, 0.063 W, 0402"
R22 R44: "RES, 240, 5%, 0.1 W, 0603"
R23 R26 R54 R59: "RES, 49.9 k, 1%, 0.063 W, 0402"
R25: "RES, 100, 5%, 0.063 W, 0402"
R27: "RES, 9.1 k, 5%, 0.063 W, 0402"
R28: "RES, 3.92 k, 1%, 0.063 W, 0402"
R29: "RES, 5.11 k, 1%, 0.063 W, 0402"
R30: "RES, 1.3 k, 5%, 0.063 W, 0402"
R35: "RES, 12 k, 5%, 0.063 W, 0402"
R37: "RES, 26.1 k, 1%, 0.063 W, 0402"
R38: "RES, 31.6 k, 1%, 0.063 W, 0402"
R40: "RES, 10.0 k, 1%, 0.063 W, 0402"
R41: "RES, 51.1, 1%, 0.063 W, 0402"
R42: "RES, 0.1, 1%, 0.125 W, 0805"
R45: "RES, 1.2 k, 5%, 0.063 W, 0402"
R46: "RES, 1.15 k, 1%, 0.063 W, 0402"
R47: "RES, 510, 5%, 0.063 W, 0402"
R49 R52 R63 R67 R68 R74 R75 R76 R77 R83 R84 R85: "RES, 10 k, 5%, 0.063 W, 0402"
R50 R55: "RES, 6.34 k, 1%, 0.063 W, 0402"
R51: "RES, 4.7 k, 5%, 0.063 W, 0402"
R53: "RES, 20 k, 5%, 0.063 W, 0402"
R56 R79: "RES, 22, 5%, 0.063 W, 0402"
R57: "RES, 309 k, 1%, 0.063 W, 0402"
R58: "RES, 10 k, 5%, 0.1 W, 0603"
R60: "RES, 23.7 k, 1%, 0.063 W, 0402"
R80 R82: "RES, 56.2, 1%, 0.125 W, 0805"
R86: "RES, 8.06 k, 1%, 0.063 W, 0402"
T2: "Transformers, Gate Drive , 785uH, SMT"
TP1 TP2 TP3: library part SMOX/060/B1LP.R3K, "Test Point, Silver, SMD"
U1: "Low-Voltage 4-Bit 1-of-2 FET Multiplexer/Demultiplexer, RSV0016A"
U2: "Buck Inverting Buck-Boost Step Down Regulator with 3.5 to 60 V Input and 0.8 to 58 V Output, -40 to 150 degC, 10-Pin SON (DRC), Green (RoHS & no Sb/Br)"
U3: "Wide Input 60-V, 200-mA Synchronous Step-Down DC-DC Converter With Low IQ, DRB0008B"
U4: "2.5 to 18 V Positive Voltage 10A Integrated Hot-Swap Controller, RUV0036A"
U5: "Dual Comparator, D0008A"
U7 U9 U12: "3.3V-Supply RS-485 with IEC ESD Protection, D0008A"

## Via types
v1: diameter 20, hole 8, Top Layer to Bottom Layer, 200 vias
v2: diameter 19, hole 7.87, Top Layer to Bottom Layer, 2 vias

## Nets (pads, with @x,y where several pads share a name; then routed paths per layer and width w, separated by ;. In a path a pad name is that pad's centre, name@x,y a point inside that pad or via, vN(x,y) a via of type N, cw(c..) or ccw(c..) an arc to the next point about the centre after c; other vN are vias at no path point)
3.3V: C26.2 C39.2 C40.2 C41.2 C42.2 D5.2 D6.2 D7.2 D8.2 D9.2 D10.2 D11.2 D15.2 J9.1 J10.1 J11.1 Q2.2 R3.2 R13.2 R14.2 R32.2 R34.2 R43.2 R51.2 R58.2 R63.2 R74.2 R75.2 R76.2 R77.2 R81.2 U1.11 U1.14 U5.8 U7.8 U9.8 U12.8 | length 6976.2
  Top Layer w10: D15.2@1030,1319.84 1032.6,1317.24 1032.6,1346.22 R14.2@1066.38,1380 1035,1380 ; v1(1885,1625) 1895.88,1614.12 R51.2@1895.88,1535 1894.5,1533.62 U5.8@1894.5,1422.28 ; R58.2@2780,2231.5 R58.2@2786.12,2237.62
  Top Layer w20: R58.2@2780,2231.5 2780,2725.97 v1(2899.28,2845.25)
  Top Layer w30: D15.2@1030,1317.74 1030,1192.2 1095.25,1126.95 1755.39,1126.95 1825,1196.56 1825,1390 1857.28,1422.28 U5.8@1894.5,1422.28
  Top Layer w50: J10.1@1770,2940 2040,2940 ; R32.2@2040,2780 2040,2940 ; J9.1@2220,2940 2040,2940
  Mid-Layer 1 w10: v1(1885,1625) v1@1890,1625
  Bottom Layer w6: C42.2@1844.37,1582.13 C42.2@1845,1581.5 1869.41,1581.5 R77.2@1909.2,1541.71
  Bottom Layer w7: U1.14@1747.87,1542.76 1747.87,1577.87 1752.13,1582.13 U1.11@1771.5,1582.13 C42.2@1844.37,1582.13
  Bottom Layer w10: J11.1@770,2790 1130,2430 1130,2370 ; 1035,1380 1070,1380 1130,1440 ; 1132.4,1902.6 D10.2@1177.24,1902.6 ; 1132.6,1582.6 D6.2@1177.24,1582.6 ; 1132.6,1742.6 D11.2@1177.24,1742.6 ; 1132.6,2062.6 D9.2@1177.24,2062.6 ; 1132.6,2222.6 D8.2@1177.24,2222.6 ; D5.2@1177.24,1422.6 1147.4,1422.6 1130,1440 ; D7.2@1177.24,2382.6 1142.6,2382.6 1130,2370 ; R63.2@1465,1741.38 1506.38,1700 1590,1700 1625,1735 ; 1655,2045 1654.32,2045.68 C40.2@1654.32,2081.39 1654.32,2140.92 U12.8@1679.79,2166.39 ; U7.8@1680.42,1845.09 1654.32,1818.99 1654.32,1761.39 1869.51,1761.39 R74.2@1909.2,1721.71 R75.2@1909.2,1661.71 R76.2@1909.2,1610 ; R77.2@1909.2,1541.71 R76.2@1909.2,1601.71 ; v1(2190,1565) 2205,1565 2213.29,1556.71 U9.8@2250.1,1556.71 2250.1,1497.5 C41.2@2224.32,1471.71 ; 1130,1440 1130,2370
  Bottom Layer w20: R3.2@2834.16,3046.5 2875.01,3046.5 2900,3022.37 2900,2823.93
  Bottom Layer w30: J9.1@2220,2940 2323.91,3043.91 R13.2@2595.09,3043.91 R43.2@2675.09,3043.91 R81.2@2755.09,3043.91 R3.2@2835.09,3043.91
  other v1: 1055,1350 1015,1355 1025,1385 2160,1580 2185,1595 1885,1685 1870,1724.09 1835,1760.49
CLK_OUT: D8.3 R10.2 R74.1 U9.4 | length 1708.4
  Mid-Layer 1 w10: v2(980,2385) 1029.21,2434.21 1454.71,2434.21 1590,2298.92 1590,2215 1835.35,1969.65 1835.35,1864.65 v2(1945,1755)
  Bottom Layer w10: v2(980,2385) 985,2385 991.5,2378.5 R10.2@991.5,2350 1055,2350 1082.76,2322.24 D8.3@1082.76,2260 ; v2(1945,1755) 1956.44,1743.56 R74.1@1956.44,1721.71 1971.44,1706.71 U9.4@2035.54,1706.71
CLOCK+: C32.1 J6.8 J7.3 R78.2 | length 1399.6
  Mid-Layer 2 w10: J7.3@3045,1645 3200,1800 3200,2093.19 J6.8@3359.37,2252.56
  Bottom Layer w10: R78.2@2391.5,1665 2392.99,1663.5 C32.1@2460,1663.5 2478.5,1645 J7.3@3045,1645
CLOCK-: C29.2 J6.15 J7.2 R73.2 | length 1614.9
  Mid-Layer 2 w10: J7.2@3045,1545 3225,1725 3225,2080 3343.62,2198.62 J6.15@3459.37,2198.62
  Bottom Layer w10: R73.2@2391.5,1595 2456.5,1595 C29.2@2460,1591.5 2492.2,1623.7 2966.3,1623.7 J7.2@3045,1545 J7.2@3030.21,1530.21
DATA+: C28.1 J6.5 J7.5 R22.1 R44.1 R66.2 | length 1699.8
  Bottom Layer w10: R66.2@1831.5,1950 1886.5,1950 C28.1@1890,1953.5 1902.01,1941.5 2035,1941.5 2077.28,1899.21 2110.79,1899.21 2189.24,1820.76 2579.24,1820.76 2651.21,1748.79 2966.26,1748.79 3045,1827.53 J7.5@3045,1845 3086.97,1886.97 3196.97,1886.97 3240,1930 3358.31,1930 J6.5@3359.37,1928.94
